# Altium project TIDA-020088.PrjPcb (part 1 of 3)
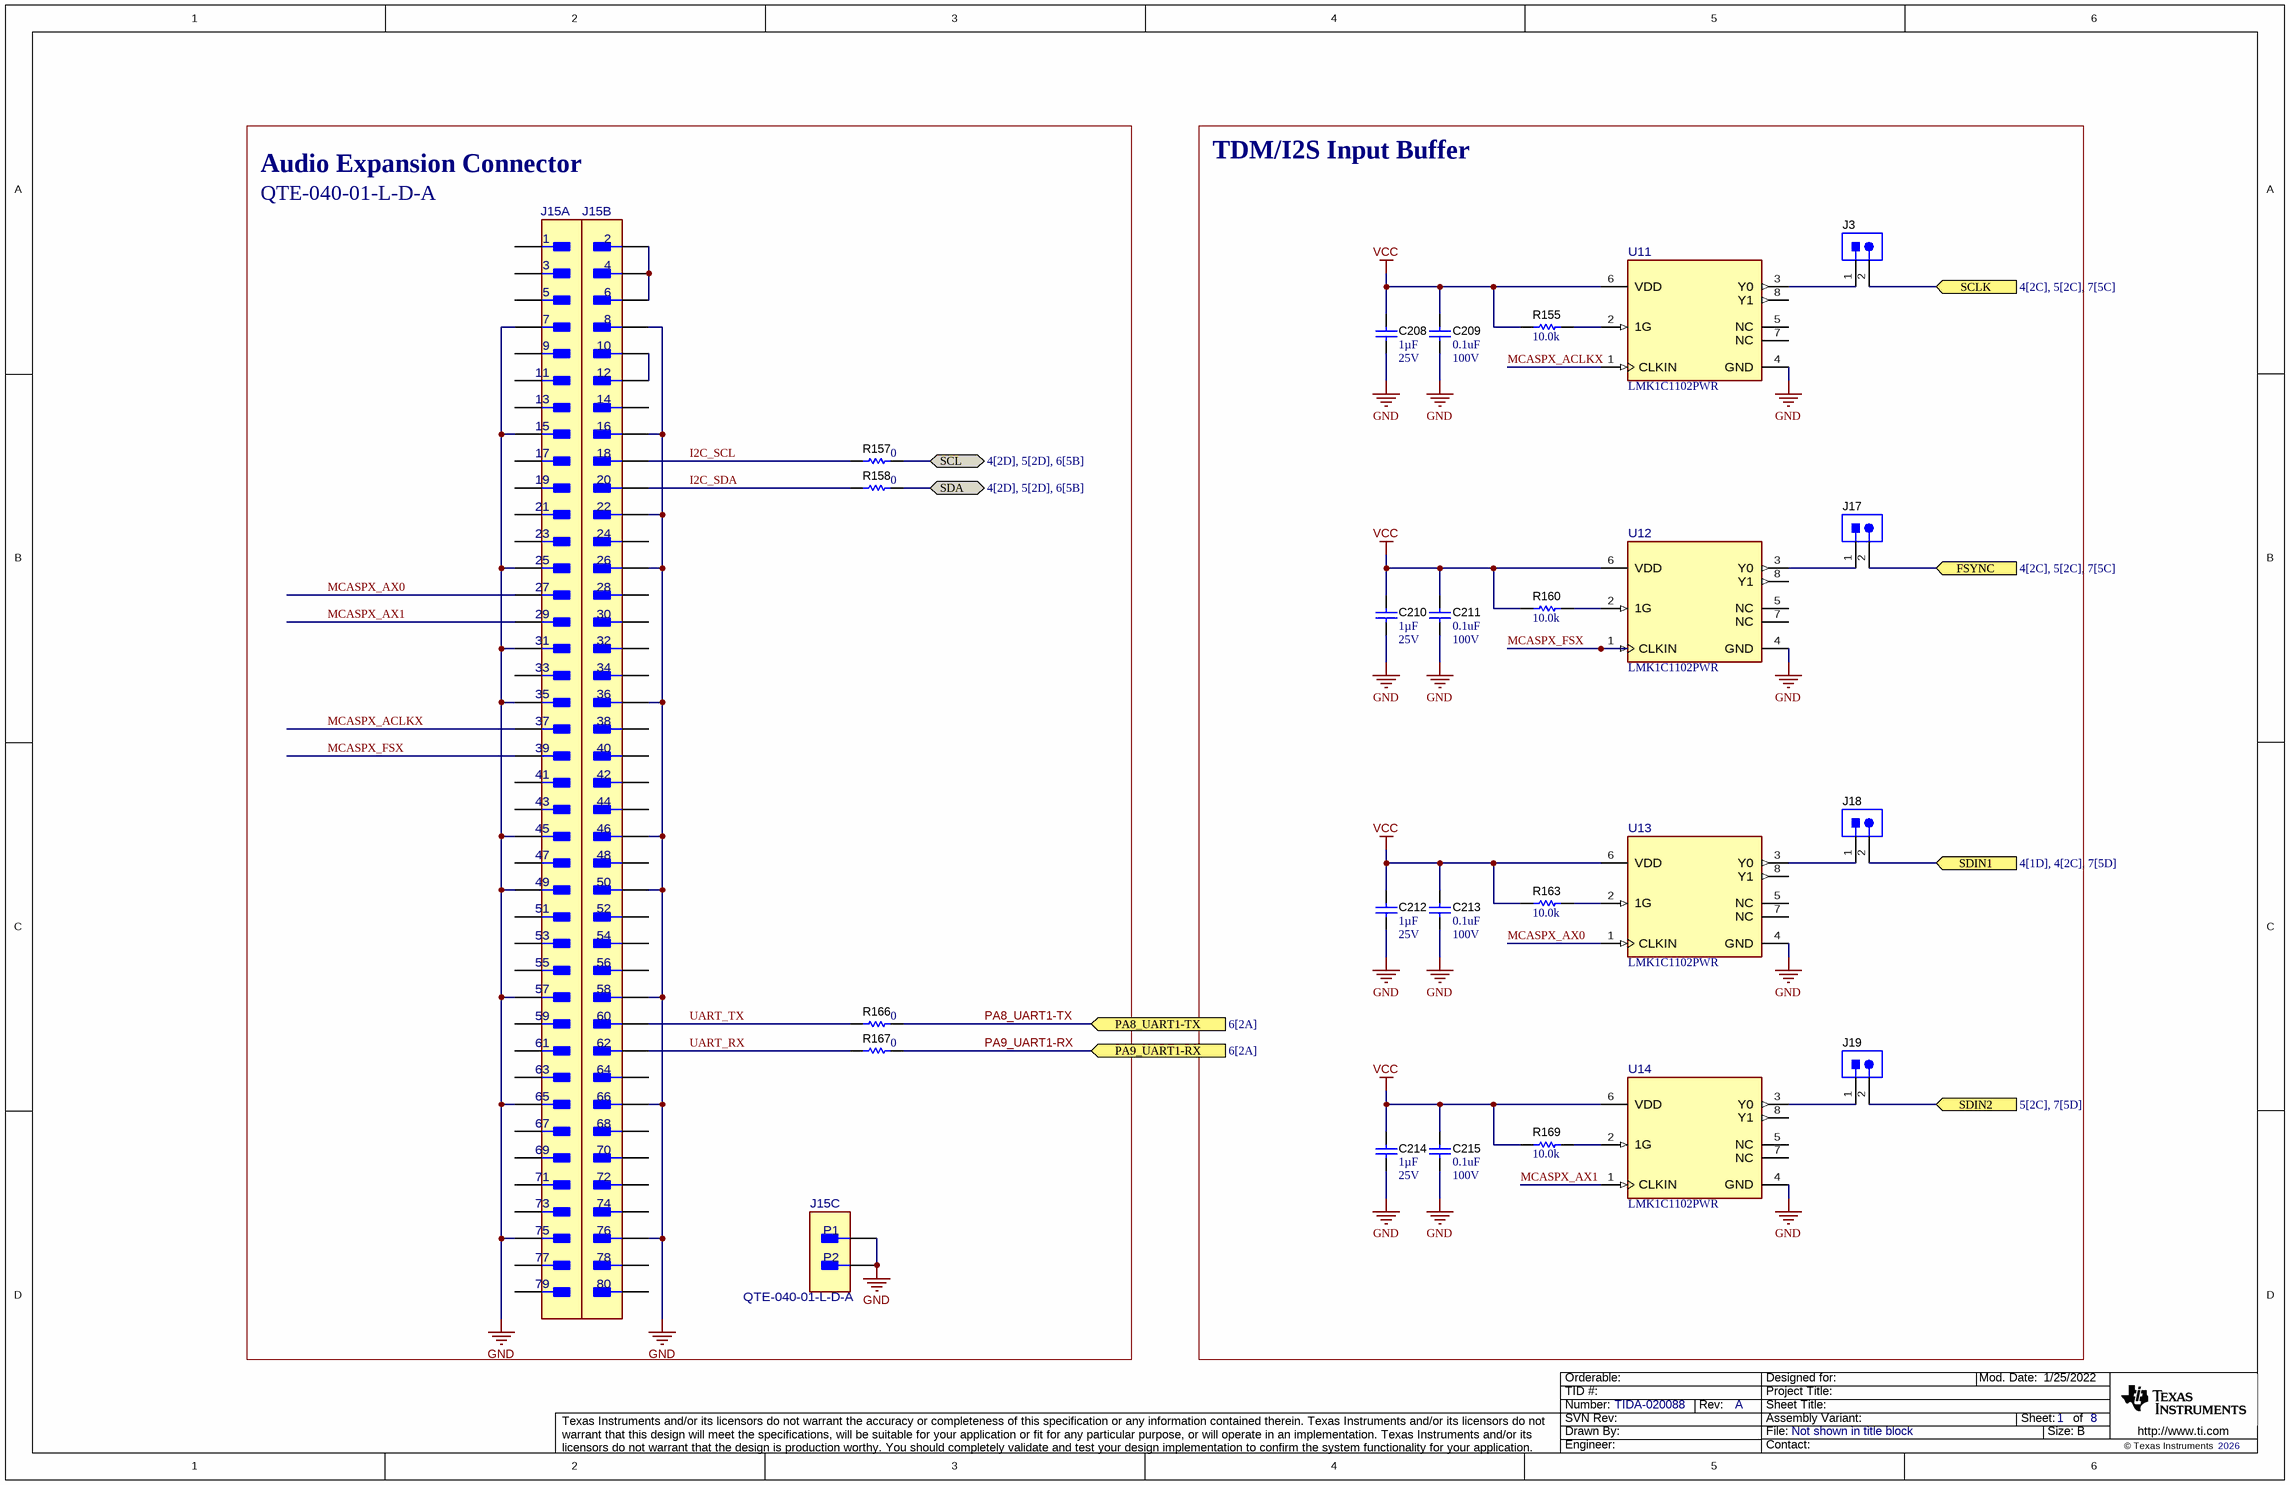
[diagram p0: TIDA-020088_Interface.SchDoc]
SCH_Rev: A; Prj_Number: TIDA-020088; CopyrightYear: 2026
8 sheets, 561 parts. Net scope: flat (ports and power ports of the same name join across sheets).
Board file: TIDA-020088.PCBDOC
Sheets:
  TIDA-020088_Interface.SchDoc
  TIDA-020088_Vbat_Input.SchDoc
  TIDA-020088_LM5125.SchDoc
  TIDA-020088_TAS6684_1.SchDoc
  TIDA-020088_TAS6684_2.SchDoc
  TIDA-020088_MCU-MSPM0G3519SPZR.SchDoc
  TIDA-020088_SPDIF and Interface.SchDoc
  Hardware.SchDoc

## Sheet TIDA-020088_Interface.SchDoc
size 431 x 279 mm; Date: Not shown in title block; ApprovedBy: Not shown in title block; CheckedBy: Not shown in title block; Author: Not shown in title block; CompanyName: Not shown in title block; Engineer: Not shown in title block; Organization: Not shown in title block; Address1: Not shown in title block; Address2: Not shown in title block; Address3: Not shown in title block; Address4: Not shown in title block; DocumentNumber: 2; Revision: Use project parameter SCH_Rev; SheetNumber: 1; SheetTotal: 8; PageSetup: Record=PageOptions¦CenterHorizontal=True¦CenterVertical=True¦PrintScale=1.00¦XCorrection=1.00¦YCorrection=1.00¦PrintKind=0¦BorderSize=5000000¦LeftOffset=0¦BottomOffset=0¦Orientation=2¦PaperLength=1000¦PaperWidth=1000¦Scale=100¦PaperSource=15¦PrintQuality=600¦MediaType=1¦DitherType=10¦PaperKind=Letter¦PrintScaleMode=1

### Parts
C208  Cap_F: 1µF  VDC_V: 25V  [0603]  (hidden comment: GCM188R71E105KA64D)
C209  ValueDisplayed: 0.1uF  VDC_V: 100V  [0603]  (hidden comment: GCJ188R72A104KA01D)
C210  Cap_F: 1µF  VDC_V: 25V  [0603]  (hidden comment: GCM188R71E105KA64D)
C211  ValueDisplayed: 0.1uF  VDC_V: 100V  [0603]  (hidden comment: GCJ188R72A104KA01D)
C212  Cap_F: 1µF  VDC_V: 25V  [0603]  (hidden comment: GCM188R71E105KA64D)
C213  ValueDisplayed: 0.1uF  VDC_V: 100V  [0603]  (hidden comment: GCJ188R72A104KA01D)
C214  Cap_F: 1µF  VDC_V: 25V  [0603]  (hidden comment: GCM188R71E105KA64D)
C215  ValueDisplayed: 0.1uF  VDC_V: 100V  [0603]  (hidden comment: GCJ188R72A104KA01D)
J3  TSW-102-07-G-S  [TSW-102-07-G-S]  (value not drawn)
J15  QTE-040-01-L-D-A  [FP-QTE-040-01-L-D-A_HDR80-MFG]  (parts A,B,C of 3)
J17  TSW-102-07-G-S  [TSW-102-07-G-S]  (value not drawn)
J18  TSW-102-07-G-S  [TSW-102-07-G-S]  (value not drawn)
J19  TSW-102-07-G-S  [TSW-102-07-G-S]  (value not drawn)
R155  ValueDisplayed: 10.0k  [0603]  (hidden comment: CRCW060310K0FKEA)
R157  ValueDisplayed: 0  [0603]  (hidden comment: CRCW06030000Z0EA)
R158  ValueDisplayed: 0  [0603]  (hidden comment: CRCW06030000Z0EA)
R160  ValueDisplayed: 10.0k  [0603]  (hidden comment: CRCW060310K0FKEA)
R163  ValueDisplayed: 10.0k  [0603]  (hidden comment: CRCW060310K0FKEA)
R166  ValueDisplayed: 0  [0603]  (hidden comment: CRCW06030000Z0EA)
R167  ValueDisplayed: 0  [0603]  (hidden comment: CRCW06030000Z0EA)
R169  ValueDisplayed: 10.0k  [0603]  (hidden comment: CRCW060310K0FKEA)
U11  LMK1C1102PWR  [PW0008A-MFG]
U12  LMK1C1102PWR  [PW0008A-MFG]
U13  LMK1C1102PWR  [PW0008A-MFG]
U14  LMK1C1102PWR  [PW0008A-MFG]

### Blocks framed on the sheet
Audio Expansion Connector: J15 R157 R158 R166 R167
TDM/I2S Input Buffer: C208-C215 J3 J17-J19 R155 R160 R163 R169 U11-U14

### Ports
FSYNC (in, see 4[2C], 5[2C], 7[5C]), PA8_UART1-TX (in, see 6[2A]), PA9_UART1-RX (in, see 6[2A]), SCL (bidir, see 4[2D], 5[2D], 6[5B]), SCLK (in, see 4[2C], 5[2C], 7[5C]), SDA (bidir, see 4[2D], 5[2D], 6[5B]), SDIN1 (in, see 4[1D], 4[2C], 7[5D]), SDIN2 (in, see 5[2C], 7[5D])

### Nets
GND: C208.1 C209.1 C210.1 C211.1 C212.1 C213.1 C214.1 C215.1 J15.7 J15.8 J15.15 J15.16 J15.22 J15.25 J15.26 J15.31 J15.35 J15.36 J15.45 J15.46 J15.49 J15.50 J15.57 J15.58 J15.65 J15.66 J15.75 J15.76 J15.P1 J15.P2 U11.4(GND) U12.4(GND) U13.4(GND) U14.4(GND)
VCC: C208.2 C209.2 C210.2 C211.2 C212.2 C213.2 C214.2 C215.2 R155.1 R160.1 R163.1 R169.1 U11.6(VDD) U12.6(VDD) U13.6(VDD) U14.6(VDD)
I2C_SCL: J15.18 R157.1
I2C_SDA: J15.20 R158.1
MCASPX_ACLKX: J15.37 U11.1(CLKIN)
MCASPX_AX0: J15.27 U13.1(CLKIN)
MCASPX_AX1: J15.29 U14.1(CLKIN)
MCASPX_FSX: J15.39 U12.1(CLKIN)
PA8_UART1-TX: R166.2 ; port PA8_UART1-TX
PA9_UART1-RX: R167.2 ; port PA9_UART1-RX
UART_RX: J15.62 R167.1
UART_TX: J15.60 R166.1
NetJ2_2: J3.2 ; port SCLK
NetJ3_1: J3.1 U11.3(Y0)
NetJ4_2: J17.2 ; port FSYNC
NetJ6_2: J18.2 ; port SDIN1
NetJ11_2: R157.2 ; port SCL
NetJ11_3: R158.2 ; port SDA
NetJ15_2: J15.2 J15.4 J15.6
NetJ15_10: J15.10 J15.12
NetJ17_1: J17.1 U12.3(Y0)
NetJ18_1: J18.1 U13.3(Y0)
NetJ19_1: J19.1 U14.3(Y0)
NetJ19_2: J19.2 ; port SDIN2
NetR155_2: R155.2 U11.2(1G)
NetR160_2: R160.2 U12.2(1G)
NetR163_2: R163.2 U13.2(1G)
NetR169_2: R169.2 U14.2(1G)

Not connected (* = marked no-connect by the designer): J15 1 3 5 9 11 13 14 17 19 21 23 24 28 30 32 33 34 38 40 41 42 43 44 47 48 51 52 53 54 55 56 59 61 63 64 67 68 69 70 71 72 73 74 77 78 79 80; U11 5(NC) 7(NC) 8(Y1); U12 5(NC) 7(NC) 8(Y1); U13 5(NC) 7(NC) 8(Y1); U14 5(NC) 7(NC) 8(Y1)

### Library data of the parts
C208 C210 C212 C214 = CMP-0007139-3: CAP, CERM, 1 uF, 25 V, +/- 10%, X7R, AEC-Q200 Grade 1, 0603; Manufacturer: MuRata; TaMin_C: -55°C; Polarized: N; SizeAreaWB_mm2: 4.68; Value1: Unknown; U/M: EA; Value: 1uF; TaMax_C: 125°C; SizeZ_mm: 1; SizeX_mm: 1.6; SizeY_mm: 0.8; SizeArea_mm2: 1.28; AEC Qualified: Y; AEC Category: Q200
C209 C211 C213 C215 = CMP-0064935-4: CAP, CERM, 0.1 uF, 100 V,+/- 10%, X7R, AEC-Q200 Grade 1, 0603; Manufacturer: MuRata; Polarized: N; Value: 0.1uF; U/M: EA; Cap_F: 100nF; Value1: Unknown; TaMin_C: -55°C; TaMax_C: 125°C; SizeAreaWB_mm2: 4.68; SizeZ_mm: 1; SizeX_mm: 1.6; SizeY_mm: 0.8; SizeArea_mm2: 1.28; AEC Qualified: Y; AEC Category: Q200
J3 J17-J19 = CMP-0075405-2: Header, 100mil, 2x1, Gold, TH; Manufacturer: Samtec; Pitch_mm: 2.54; Cert_VDE: N; Gender: Male; Cert_CSA: Y; Voltage_V: 550V; Green_REACh: Passed; Current_A: 6.3A; Green_Lifecycle: Active; Row_Count: 1
J15 = CMP-0091968-1: 80 Position Connector Header, Outer Shroud Contacts Surface Mount Gold; Manufacturer: Samtec; SizeZ_mm: 4.347mm; AEC Qualified: No; Conn Gender: Male; Voltage_V: 225V; Row_Count: 2; ContactFinish: Gold,Nickel; Is Female: yes; Conn Orientation: Vertical; DUT-Pitch_mm: 0.8mm
R155 R160 R163 R169 = CMP-0021998-4: RES, 10.0 k, 1%, 0.1 W, AEC-Q200 Grade 0, 0603; Manufacturer: Vishay-Dale; Power_W: 100mW; TempCo: 100 ppm/C; Value_Code: 10k0; Value: 10.0k; EIA_Code: E96; Res_ohm: 10k; SizeX_mm: 1.6; SizeY_mm: 0.8; SizeZ_mm: 1; Value2: 0.1W; SizeArea_mm2: 1.28; AEC Qualified: Y; VDC_V: 75V; AEC Category: Q200; AEC Grade: 0
R157 R158 R166 R167 = CMP-0025697-4: RES, 0, 5%, 0.1 W, AEC-Q200 Grade 0, 0603; Manufacturer: Vishay-Dale; Power_W: 100mW; TempCo: 200 ppm/C; Value_Code: 0000; Value: 0; SizeX_mm: 1.6; SizeY_mm: 0.8; SizeZ_mm: 1; Value2: 0.1W; SizeArea_mm2: 1.28; AEC Qualified: Y; AEC Category: Q200; EIA_Code: E24; VDC_V: 75V
U11-U14 = CMP-0091149-1: Clock Clock Buffer IC 1:4 250MHz 8-TSSOP (0.173", 4.40mm Width); Manufacturer: Texas Instruments; Standoff Height: 0.05mm; SizeZ_mm: 1.2mm; Propagation Delay: 1.5ns; AEC Qualified: No; Number Of Outputs: 2; Nominal Supply Current: 25-33000uA; TaMin_C: -40°C; Min Supply Voltage: 1.71V; Max Supply Voltage: 3.465V; Number Of Elements: 1; TJmax_C: +150°C; TaMax_C: +125°C

## Sheet TIDA-020088_Vbat_Input.SchDoc
size 431 x 279 mm; Date: Not shown in title block; ApprovedBy: Not shown in title block; CheckedBy: Not shown in title block; Author: Not shown in title block; CompanyName: Not shown in title block; Engineer: Not shown in title block; Organization: Not shown in title block; Address1: Not shown in title block; Address2: Not shown in title block; Address3: Not shown in title block; Address4: Not shown in title block; DocumentNumber: 2; Revision: Use project parameter SCH_Rev; SheetNumber: 2; SheetTotal: 8; PageSetup: Record=PageOptions¦CenterHorizontal=True¦CenterVertical=True¦PrintScale=1.00¦XCorrection=1.00¦YCorrection=1.00¦PrintKind=0¦BorderSize=5000000¦LeftOffset=0¦BottomOffset=0¦Orientation=2¦PaperLength=1000¦PaperWidth=1000¦Scale=100¦PaperSource=15¦PrintQuality=600¦MediaType=1¦DitherType=10¦PaperKind=Letter¦PrintScaleMode=1
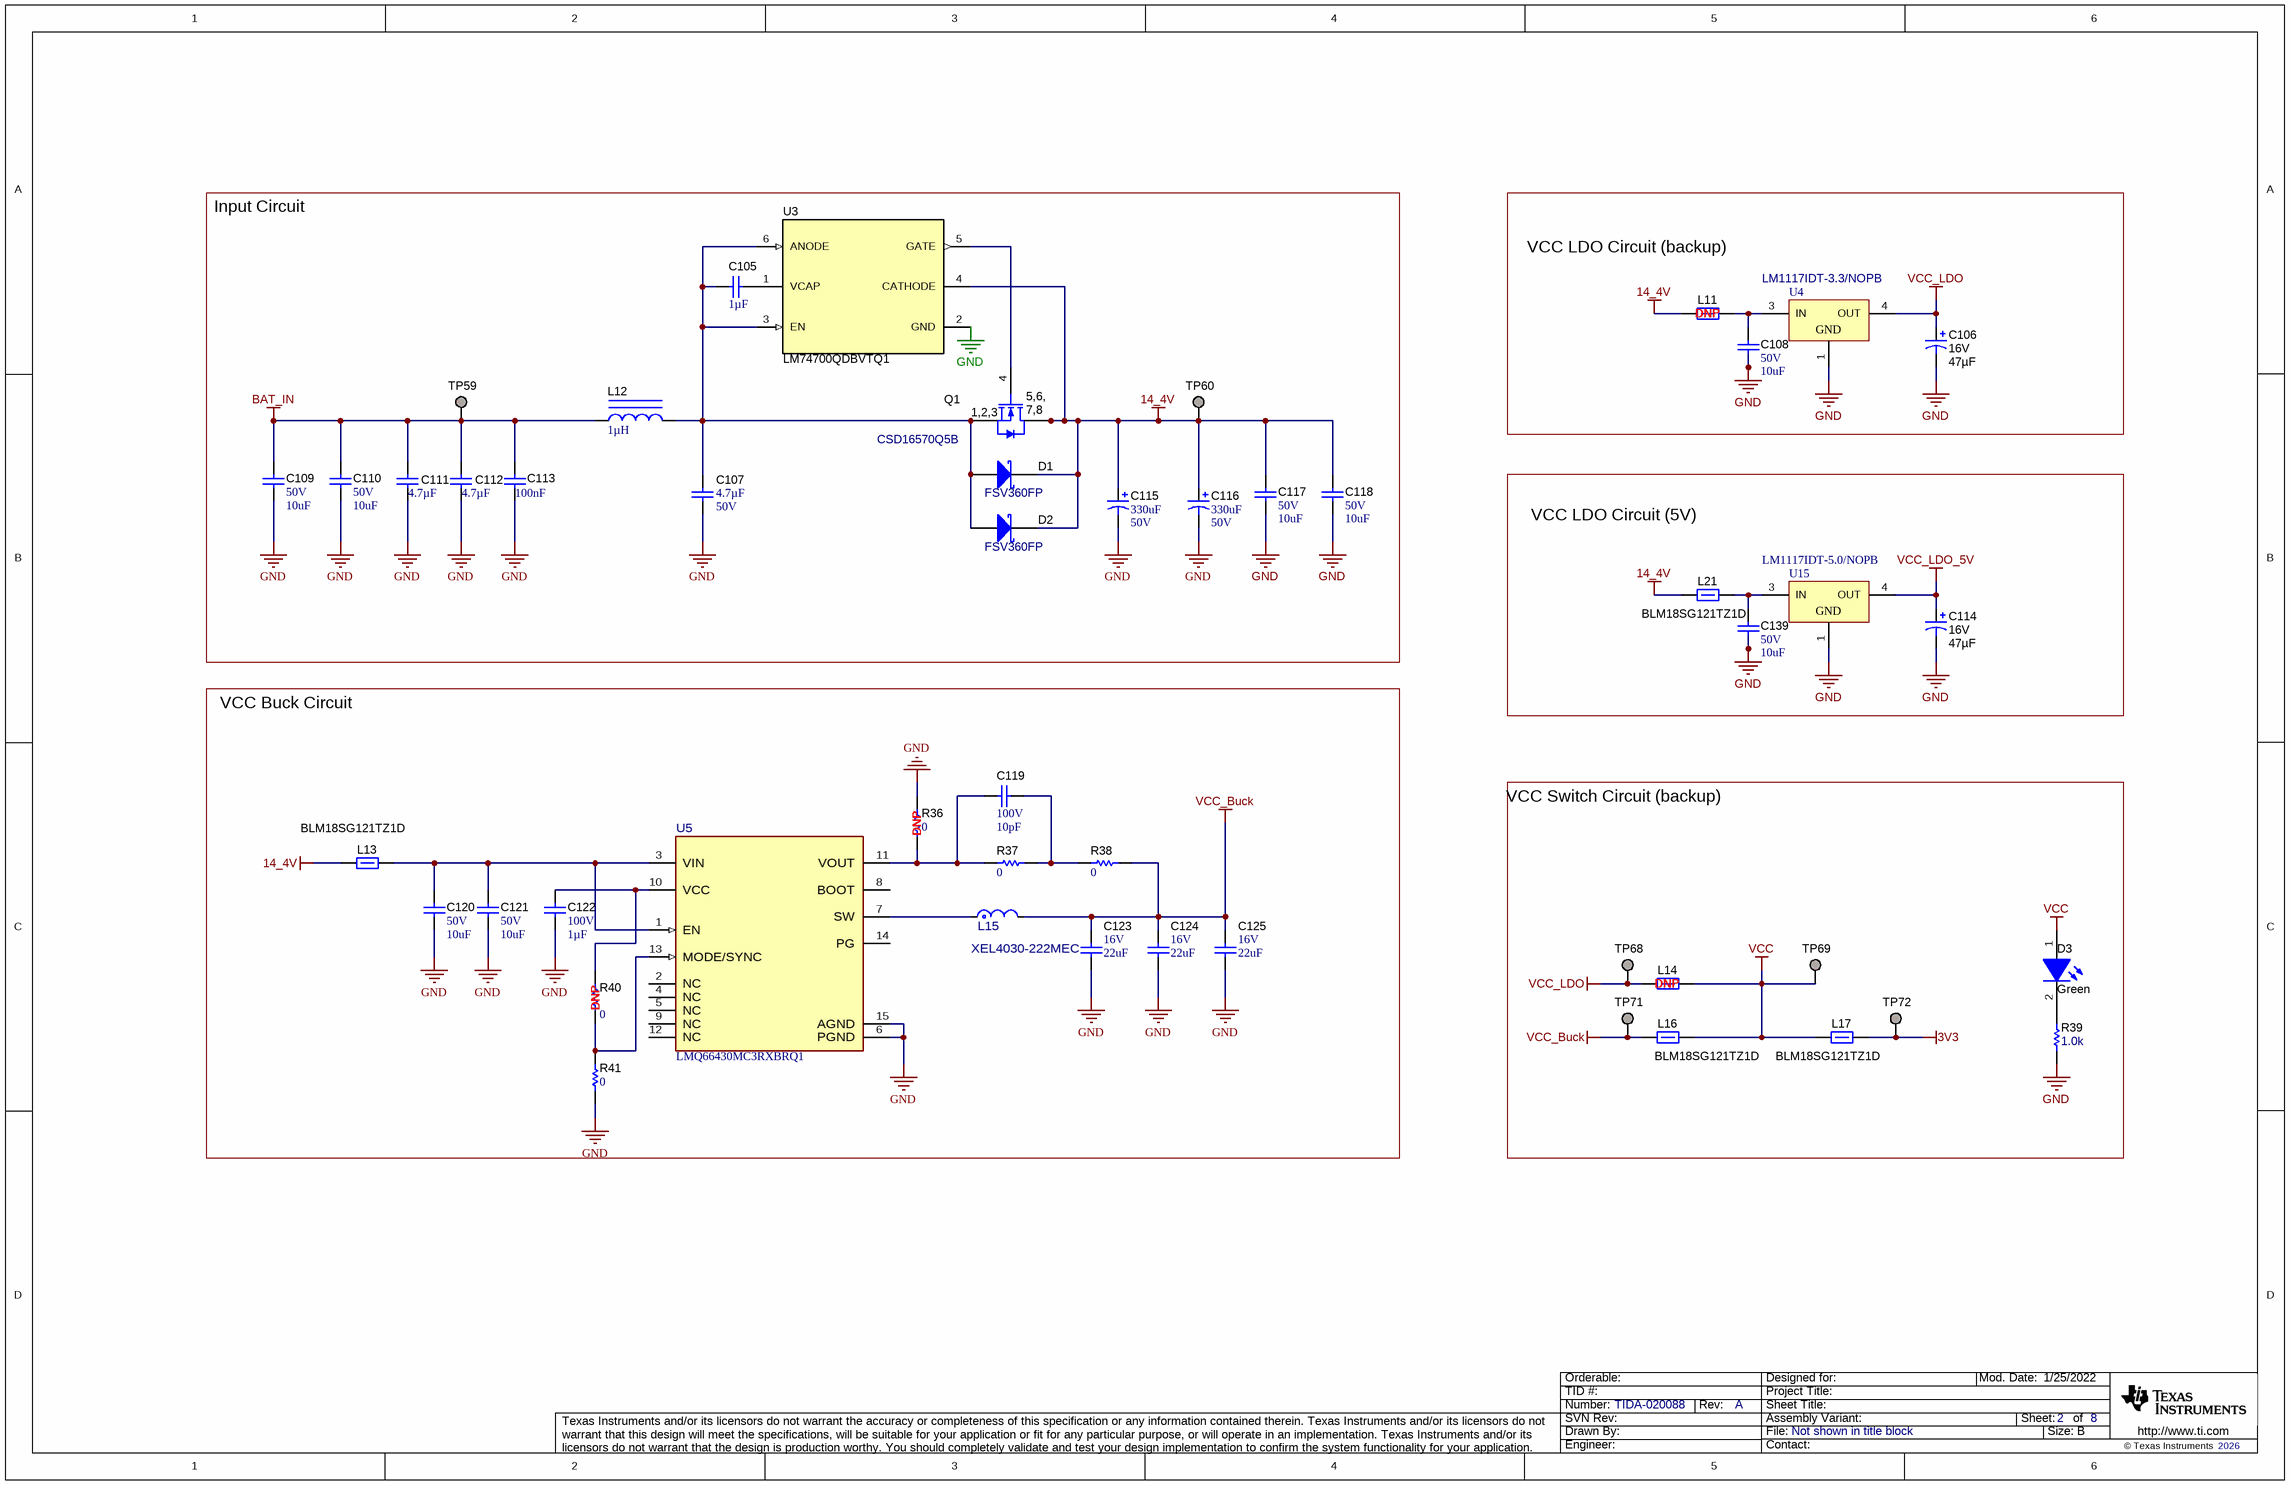
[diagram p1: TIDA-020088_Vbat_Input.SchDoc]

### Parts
C105  Cap_F: 1µF  [0603]  (hidden comment: GCM188R71E105KA64D)
C106  VDC_V: 16V  ValueDisplayed: 47µF  [Panasonic_B]  (hidden comment: EEE-FT1C470AR)
C107  VDC_V: 50V  ValueDisplayed: 4.7µF  [1210_270]  (hidden comment: GCM32ER71H475KA55L)
C108  VDC_V: 50V  ValueDisplayed: 10uF  [1210_280]  (hidden comment: UMK325AB7106KMHT)
C109  VDC_V: 50V  ValueDisplayed: 10uF  [1210_280]  (hidden comment: UMK325AB7106KMHT)
C110  VDC_V: 50V  ValueDisplayed: 10uF  [1210_280]  (hidden comment: UMK325AB7106KMHT)
C111  ValueDisplayed: 4.7µF  [1210_270]  (hidden comment: GCM32ER71H475KA55L)
C112  ValueDisplayed: 4.7µF  [1210_270]  (hidden comment: GCM32ER71H475KA55L)
C113  Cap_F: 100nF  [0603]  (hidden comment: GCJ188R72A104KA01D)
C114  VDC_V: 16V  ValueDisplayed: 47µF  [Panasonic_B]  (hidden comment: EEE-FT1C470AR)
C115  ValueDisplayed: 330uF  VDC_V: 50V  [Nichicon_1000x1000]  (hidden comment: UCM1H331MNL1GS)
C116  ValueDisplayed: 330uF  VDC_V: 50V  [Nichicon_1000x1000]  (hidden comment: UCM1H331MNL1GS)
C117  VDC_V: 50V  ValueDisplayed: 10uF  [1210_280]  (hidden comment: UMK325AB7106KMHT)
C118  VDC_V: 50V  ValueDisplayed: 10uF  [1210_280]  (hidden comment: UMK325AB7106KMHT)
C119  VDC_V: 100V  ValueDisplayed: 10pF  [0603]  (hidden comment: GCM1885C2A100JA16D)
C120  VDC_V: 50V  ValueDisplayed: 10uF  [1210_280]  (hidden comment: UMK325AB7106KMHT)
C121  VDC_V: 50V  ValueDisplayed: 10uF  [1210_280]  (hidden comment: UMK325AB7106KMHT)
C122  VDC_V: 100V  ValueDisplayed: 1µF  [1206]  (hidden comment: GCJ31CR72A105KA01K)
C123  VDC_V: 16V  ValueDisplayed: 22uF  [1210_280]  (hidden comment: CGA6P1X7R1C226M250AC)
C124  VDC_V: 16V  ValueDisplayed: 22uF  [1210_280]  (hidden comment: CGA6P1X7R1C226M250AC)
C125  VDC_V: 16V  ValueDisplayed: 22uF  [1210_280]  (hidden comment: CGA6P1X7R1C226M250AC)
C139  VDC_V: 50V  ValueDisplayed: 10uF  [1210_280]  (hidden comment: UMK325AB7106KMHT)
D1  FSV360FP  [SOD-123HE]
D2  FSV360FP  [SOD-123HE]
D3  value Green  [LTST-C170KGKT_Green]  (hidden comment: CMP-0002888-1)
L11  DNP  [0603]  (no BOM)
L12  ValueDisplayed: 1µH  [SRP2313AA]  (hidden comment: SRP2313AA-1R0M)
L13  BLM18SG121TZ1D  [0603]
L14  DNP  [0603]  (no BOM)
L15  XEL4030-222MEC  [FP-XEL4030-222MEC_SMT2_4MM0_4MM0-MFG]
L16  BLM18SG121TZ1D  [0603]
L17  BLM18SG121TZ1D  [0603]
L21  BLM18SG121TZ1D  [0603]
Q1  CSD16570Q5B  [DNK0008A]
R36  DNP  ValueDisplayed: 0  [0603]  (no BOM)
R37  ValueDisplayed: 0  [0603]  (hidden comment: CRCW06030000Z0EA)
R38  ValueDisplayed: 0  [0603]  (hidden comment: CRCW06030000Z0EA)
R39  ValueDisplayed: 1.0k  [0402L]  (hidden comment: CRCW04021K00JNED)
R40  DNP  ValueDisplayed: 0  [0603]  (no BOM)
R41  ValueDisplayed: 0  [0603]  (hidden comment: CRCW06030000Z0EA)
TP59  TP_SM_1MM  [TP_SM_1MM]  (value not drawn)  (no BOM)
TP60  TP_SM_1MM  [TP_SM_1MM]  (value not drawn)  (no BOM)
TP68  TP_SM_1MM  [TP_SM_1MM]  (value not drawn)  (no BOM)
TP69  TP_SM_1MM  [TP_SM_1MM]  (value not drawn)  (no BOM)
TP71  TP_SM_1MM  [TP_SM_1MM]  (value not drawn)  (no BOM)
TP72  TP_SM_1MM  [TP_SM_1MM]  (value not drawn)  (no BOM)
U3  LM74700QDBVTQ1  [DBV0006A_N]
U4  LM1117IDT-3.3/NOPB  [NDP0003B_N]
U5  LMQ66430MC3RXBRQ1  [RXB0014A-MFG]
U15  LM1117IDT-5.0/NOPB  [NDP0003B]

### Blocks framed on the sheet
Input Circuit: C105 C107 C109-C113 C115-C118 D1 D2 L12 Q1 TP59 TP60 U3
VCC LDO Circuit (backup): C106 C108 L11 U4
VCC LDO Circuit (5V): C114 C139 L21 U15
VCC Buck Circuit: C119-C125 L13 L15 R36-R38 R40 R41 U5
VCC Switch Circuit (backup): D3 L14 L16 L17 R39 TP68 TP69 TP71 TP72

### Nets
3V3: L17.2 TP72.1
14_4V: C115.1(+) C116.1(+) C117.1 C118.1 D1.1(K) D2.1(K) L11.1 L13.1 L21.1 Q1.5(D) Q1.6(D) Q1.7(D) Q1.8(D) Q1.9(D) TP60.1 U3.4(CATHODE)  [project net BIAS]
BAT_IN: C109.1 C110.1 C111.1 C112.1 C113.1 L12.1 TP59.1
GND: C106.2(-) C107.2 C108.2 C109.2 C110.2 C111.2 C112.2 C113.2 C114.2(-) C115.2(-) C116.2(-) C117.2 C118.2 C120.2 C121.2 C122.2 C123.2 C124.2 C125.2 C139.2 R36.2 R39.1 R41.1 U3.2(GND) U4.1(GND) U5.6(PGND) U5.15(AGND) U15.1(GND)
VCC: D3.1(A) L14.2 L16.2 L17.1 TP69.1
VCC_Buck: C123.1 C124.1 C125.1 L15.2 L16.1 R38.2 TP71.1
VCC_LDO: C106.1(+) L14.1 TP68.1 U4.4(OUT)
VCC_LDO_5V: C114.1(+) U15.4(OUT)
NetC105_1: C105.1 C107.1 D1.2(A) D2.2(A) L12.2 Q1.1(S) Q1.2(S) Q1.3(S) U3.3(EN) U3.6(ANODE)
NetC105_2: C105.2 U3.1(VCAP)
NetC108_1: C108.1 L11.2 U4.3(IN)
NetC119_1: C119.1 R36.1 R37.1 U5.11(VOUT)
NetC119_2: C119.2 R37.2 R38.1
NetC120_1: C120.1 C121.1 L13.2 U5.1(EN) U5.3(VIN)
NetC122_1: C122.1 R40.1 U5.10(VCC)
NetC139_1: C139.1 L21.2 U15.3(IN)
NetD3_2: D3.2(K) R39.2
NetL15_1: L15.1 U5.7(SW)
NetQ1_4: Q1.4(G) U3.5(GATE)
NetR40_2: R40.2 R41.2 U5.13(MODE/SYNC)

Not connected (* = marked no-connect by the designer): U5 2(NC) 4(NC) 5(NC) 8(BOOT) 9(NC) 12(NC) 14(PG)

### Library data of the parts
C105 = CMP-0007139-4: CAP, CERM, 1 uF, 25 V, +/- 10%, X7R, AEC-Q200 Grade 1, 0603; Manufacturer: MuRata; Value: 1uF; SizeZ_mm: 1; AEC Qualified: Y; VDC_V: 25V; TaMin_C: -55°C; Polarized: N; SizeAreaWB_mm2: 4.68; Value1: Unknown; U/M: EA; TaMax_C: 125°C; SizeX_mm: 1.6; SizeY_mm: 0.8; SizeArea_mm2: 1.28; AEC Category: Q200
C106 C114 = CMP-0860542-1: CAP, AL, 47 µF, 16 V, +/- 20%, 0.85 ohm, AEC-Q200 Grade 2, SMD; Manufacturer: Panasonic; AEC Qualified: Y; AEC Grade: 2; U/M: EA; SizeZ_mm: 6.1; ESR_ohm: 0.85; SizeY_mm: 4.3; CompType: Capacitor; TaMax_C: 105°C; TaMin_C: -55°C; IRMS_A: 160mA; SizeArea_mm2: 18.49; Value: 47uF; SizeAreaWB_mm2: 28.09; AEC Category: Q200; Cap_Case: B
C107 = CMP-0750153-1: CAP, CERM, 4.7 µF, 50 V,+/- 10%, X7R, AEC-Q200 Grade 1, 1210; Manufacturer: MuRata; TaMin_C: -55°C; Polarized: N; SizeAreaWB_mm2: 14.7; U/M: EA; Value: 4.7uF; TaMax_C: 125°C; SizeZ_mm: 2.7; SizeX_mm: 3.2; SizeY_mm: 2.5; Cap_Case: 1210; SizeArea_mm2: 8; AEC Qualified: Y; AEC Category: Q200; AEC Grade: 1
C108-C110 C117 C118 C120 C121 C139 = CMP-0009258-2: CAP, CERM, 10 uF, 50 V, +/- 10%, X7R, AEC-Q200 Grade 1, 1210; Manufacturer: Taiyo Yuden; Value: 10uF; SizeZ_mm: 2.8; AEC Qualified: Y; Cap_F: 10µF; AEC Grade: 1; TaMin_C: -55°C; Polarized: N; SizeAreaWB_mm2: 14.7; Value1: Unknown; U/M: EA; TaMax_C: 125°C; SizeX_mm: 3.2; SizeY_mm: 2.5; Cap_Case: 1210; SizeArea_mm2: 8; AEC Category: Q200
C111 C112 = CMP-0750153-1: CAP, CERM, 4.7 µF, 50 V,+/- 10%, X7R, AEC-Q200 Grade 1, 1210; Manufacturer: MuRata; TaMin_C: -55°C; Polarized: N; SizeAreaWB_mm2: 14.7; U/M: EA; Value: 4.7uF; TaMax_C: 125°C; SizeZ_mm: 2.7; SizeX_mm: 3.2; SizeY_mm: 2.5; Cap_Case: 1210; Value2: 50V; SizeArea_mm2: 8; AEC Qualified: Y; AEC Category: Q200; AEC Grade: 1
C113 = CMP-0064935-4: CAP, CERM, 0.1 uF, 100 V,+/- 10%, X7R, AEC-Q200 Grade 1, 0603; Manufacturer: MuRata; TaMin_C: -55°C; Polarized: N; SizeAreaWB_mm2: 4.68; Value1: Unknown; U/M: EA; Value: 0.1uF; TaMax_C: 125°C; SizeZ_mm: 1; SizeX_mm: 1.6; SizeY_mm: 0.8; Value2: 100V; SizeArea_mm2: 1.28; AEC Qualified: Y; AEC Category: Q200
C115 C116 = CMP-0064900-1: CAP, AL, 330 uF, 50 V, +/- 20%, SMD; Manufacturer: Nichicon; AEC Qualified: N; Cap_F: 330µF; IRMS_A: 900mA; SizeZ_mm: 10.8; Value: 330uF; TaMin_C: -55°C; Polarized: Y; SizeAreaWB_mm2: 151.29; Value1: Unknown; U/M: EA; TaMax_C: 105°C; SizeX_mm: 10.3; Cap_Case: 10x10mm; SizeArea_mm2: 106.09; CompType: Capacitor; AEC Category: Q200
C119 = CMP-0084283-1: CAP, CERM, 10 pF, 100 V,+/- 5%, C0G/NP0, AEC-Q200 Grade 1, 0603; Manufacturer: MuRata; TaMin_C: -55°C; Polarized: N; SizeAreaWB_mm2: 4.68; U/M: EA; Value: 10pF; TaMax_C: 125°C; SizeZ_mm: 1; SizeX_mm: 1.6; SizeY_mm: 0.8; SizeArea_mm2: 1.28; AEC Qualified: Y; AEC Category: Q200
C122 = CMP-0750040-1: CAP, CERM, 1 µF, 100 V,+/- 10%, X7R, AEC-Q200 Grade 1, 1206; Manufacturer: MuRata; Value: 1uF; U/M: EA; SizeX_mm: 3.2; Polarized: N; TaMin_C: -55°C; SizeZ_mm: 1.35; SizeY_mm: 1.6; AEC Category: Q200; SizeArea_mm2: 5.12; TaMax_C: 125°C; AEC Grade: 1; AEC Qualified: Y; SizeAreaWB_mm2: 10.92
C123-C125 = CMP-0009154-2: CAP, CERM, 22 uF, 16 V, +/- 20%, X7R, AEC-Q200 Grade 1, 1210; Manufacturer: TDK; Cap_F: 22µF; AEC Qualified: Y; AEC Grade: 1; Value: 22uF; SizeZ_mm: 2.8; TaMin_C: -55°C; ESR_ohm: 2.582m; Polarized: N; SizeAreaWB_mm2: 14.7; Value1: 0.002582 ohm; U/M: EA; TaMax_C: 125°C; SizeX_mm: 3.2; SizeY_mm: 2.5; SizeArea_mm2: 8; IRMS_A: 4.5756A; AEC Category: Q200
D1 D2 = CMP-0028825-2: Diode, Schottky, 60 V, 3 A, AEC-Q101, SOD-123HE; Manufacturer: Fairchild Semiconductor; Vf_V: 650mV; SizeArea_mm2: 6.66; Vr_V: 60V; Green_Lifecycle: Not Set; Value: 60V; Value1: 3A; Green_REACh: Incomplete; SizeY_mm: 1.8; Value2: 0.65V; TJmax_C: 150°C; AEC Category: Q101; SizeAreaWB_mm2: 13.16; SizeZ_mm: 1; AEC Qualified: Y; SizeX_mm: 3.7
D3 = CMP-0002888-1: LED, Green, SMD; Manufacturer: Lite-On; PartNumber: LTST-C170KGKT; Type: AlInGaP; Vf_V: 2V; Io_A: 20mA; Value1: W; U/M: EA
L11 L14 = CMP-0084877-1: Inductor, Ferrite Bead, Ferrite, 3 A, 120 ohm, AEC-Q200 Grade 1, SMD; Manufacturer: MuRata; PartNumber: BLM18SG121TZ1D; SizeAreaWB_mm2: 4.68; DCR_ohm: 120; Value1: 120 ohm; Imax_A: 3A; SizeZ_mm: 1; SizeX_mm: 1.6; SizeY_mm: 0.8; SizeArea_mm2: 1.28; AEC Qualified: Y; AEC Category: Q200
L12 = CMP-0081035-1: Inductor, Shielded, Metal Composite, 1 µH, 60 A, 0.00095 ohm, AEC-Q200 Grade 0, SMD; Manufacturer: Bourns; Isat: 60A @ 30% inductance drop; Irms: 70A @ 40C rise; SizeAreaWB_mm2: 612; DCR_ohm: 950µ; Value: 1uH; Imax_A: 60A; SizeZ_mm: 13; SizeX_mm: 23.5; SizeY_mm: 22; SizeArea_mm2: 517; AEC Qualified: Y; AEC Grade: 0; AEC Category: Q200
L13 L16 L17 L21 = CMP-0084877-1: Inductor, Ferrite Bead, Ferrite, 3 A, 120 ohm, AEC-Q200 Grade 1, SMD; Manufacturer: MuRata; SizeAreaWB_mm2: 4.68; DCR_ohm: 120; Value1: 120 ohm; Imax_A: 3A; SizeZ_mm: 1; SizeX_mm: 1.6; SizeY_mm: 0.8; SizeArea_mm2: 1.28; AEC Qualified: Y; AEC Category: Q200
L15 = CMP-0120010-1: Ultra-Low Loss Shielded Power Inductors 2.2µH ±20% 7.8A 22.1mOhms; Manufacturer: Coilcraft; AEC Grade: Grade 1; AEC Qualified: Yes; DCR_ohm: 22.1m; Isat: 6.1A; Material: Composite; SizeZ_mm: 3.1mm; Value: 2.2uH; Self Resonant Frequency: 40MHz; Shrouded: true; TaMax_C: +125°C; TaMin_C: -40°C; Test Frequency: 1MHz
Q1 = CMP-0000274-1: MOSFET, N-CH, 25 V, 100 A, DNK0008A (VSON-CLIP-8); Alternate Manufacturer: None; Manufacturer: Texas Instruments; SizeZ_mm: 1; ChType: N; Value2: 192 nC; Value1: 0; VdsMax_V: 25V; SizeX_mm: 6; SizeY_mm: 5; Vgs_V: 20V; Value: 25V; Rdson45_ohm: 800µ; SizeArea_mm2: 30; AEC Category: Q101; IdsMax_A: 100A; SizeAreaWB_mm2: 56; U/M: EA; QgTyp_nC: 192
R36 R40 = CMP-0025697-4: RES, 0, 5%, 0.1 W, AEC-Q200 Grade 0, 0603; Manufacturer: Vishay-Dale; PartNumber: CRCW06030000Z0EA; Power_W: 100mW; TempCo: 200 ppm/C; Value_Code: 0000; Value: 0; EIA_Code: E24; SizeX_mm: 1.6; SizeY_mm: 0.8; SizeZ_mm: 1; Value2: 0.1W; SizeArea_mm2: 1.28; AEC Qualified: Y; AEC Category: Q200; VDC_V: 75V
R37 R38 R41 = CMP-0025697-4: RES, 0, 5%, 0.1 W, AEC-Q200 Grade 0, 0603; Manufacturer: Vishay-Dale; Power_W: 100mW; TempCo: 200 ppm/C; Value_Code: 0000; Value: 0; EIA_Code: E24; SizeX_mm: 1.6; SizeY_mm: 0.8; SizeZ_mm: 1; Value2: 0.1W; SizeArea_mm2: 1.28; AEC Qualified: Y; AEC Category: Q200; VDC_V: 75V
R39 = CMP-0026852-3: RES, 1.0 k, 5%, 0.063 W, AEC-Q200 Grade 0, 0402; Manufacturer: Vishay-Dale; Power_W: 63mW; TempCo: 200 ppm/C; Value_Code: 1k00; Value: 1.0k; EIA_Code: E24; Res_ohm: 1k; SizeX_mm: 1; SizeY_mm: 0.5; SizeZ_mm: 0.6; Value2: 0.063W; CompType: Resistor; AEC Qualified: Y; VDC_V: 50V; AEC Category: Q200; AEC Grade: 0
TP59 TP60 TP68 TP69 TP71 TP72 = CMP-0003825-1: 1mm Test Point, SMT; Manufacturer: Any
U3 = CMP-0079180-1: Low Iq Always ON Smart Diode Controller, DBV0006A (SOT-23-6); Alternate PartNumber: LM74700QDBVRQ1; Alternate Manufacturer: Texas Instruments; SizeAreaWB_mm2: 14.82; SizeZ_mm: 1.45; SizeX_mm: 2.8; SizeY_mm: 2.9; SizeArea_mm2: 8.12; CompType: IC; AEC Qualified: Y; AEC Category: Q200
U4 = CMP-0070332-1: 800mA Low-Dropout Linear Regulator, 3-pin TO-252, Pb-Free; Manufacturer: Texas Instruments; CompType: LDO IC; PackageTopMarking: NSUZXYTT*LM1117*IDT-3.3; PowerWise: N
U5 = CMP-0093580-1: 3 V-36 V, 3-A Synchronous Buck Converter Optimized for Ultra Low EMI and Light Load Efficiency; Manufacturer: Texas Instruments; SizeZ_mm: 0.7mm; Min Supply Voltage: 3.6V; Number Of Outputs: 1; TaMin_C: -40°C; AEC Qualified: Yes; Output Voltage: 1-34.2V; Max Duty Cycle: 98%; Output Type: AdjustableProgrammable; Switching Frequency: 0.25-2.2MHz; Nominal Supply Current: 0.2-3uA; Max Supply Voltage: 36V; AEC Grade: Grade 1; Standoff Height: 0mm; TJmax_C: +150°C; TaMax_C: +125°C
U15 = CMP-0070337-2: Space Saving 800mA Low-Dropout Linear Regulator with Internal Current Limit, NDP0003B (TO-252-3); Manufacturer: Texas Instruments; CompType: IC; AEC Category: Q200; AEC Qualified: N; SizeAreaWB_mm2: 102.2; SizeArea_mm2: 65.2; SizeX_mm: 9.91; SizeY_mm: 6.58; SizeZ_mm: 2.55

## Sheet TIDA-020088_LM5125.SchDoc: Schematc
size 558 x 431 mm; Date: Not shown in title block; ApprovedBy: Not shown in title block; CheckedBy: Not shown in title block; Author: Not shown in title block; CompanyName: Not shown in title block; DrawnBy: Harry Hofner; Engineer: Not shown in title block; Organization: Not shown in title block; Address1: Not shown in title block; Address2: Not shown in title block; Address3: Not shown in title block; Address4: Not shown in title block; DocumentNumber: 1; Revision: Use project parameter SCH_Rev; SheetNumber: 4; SheetTotal: 8; PageSetup: Record=PageOptions¦CenterHorizontal=True¦CenterVertical=True¦PrintScale=1.00¦XCorrection=1.00¦YCorrection=1.00¦PrintKind=0¦BorderSize=5000000¦LeftOffset=0¦BottomOffset=0¦Orientation=2¦PaperLength=1000¦PaperWidth=1000¦Scale=100¦PaperSource=15¦PrintQuality=600¦MediaType=1¦DitherType=10¦PaperKind=Letter¦PrintScaleMode=1
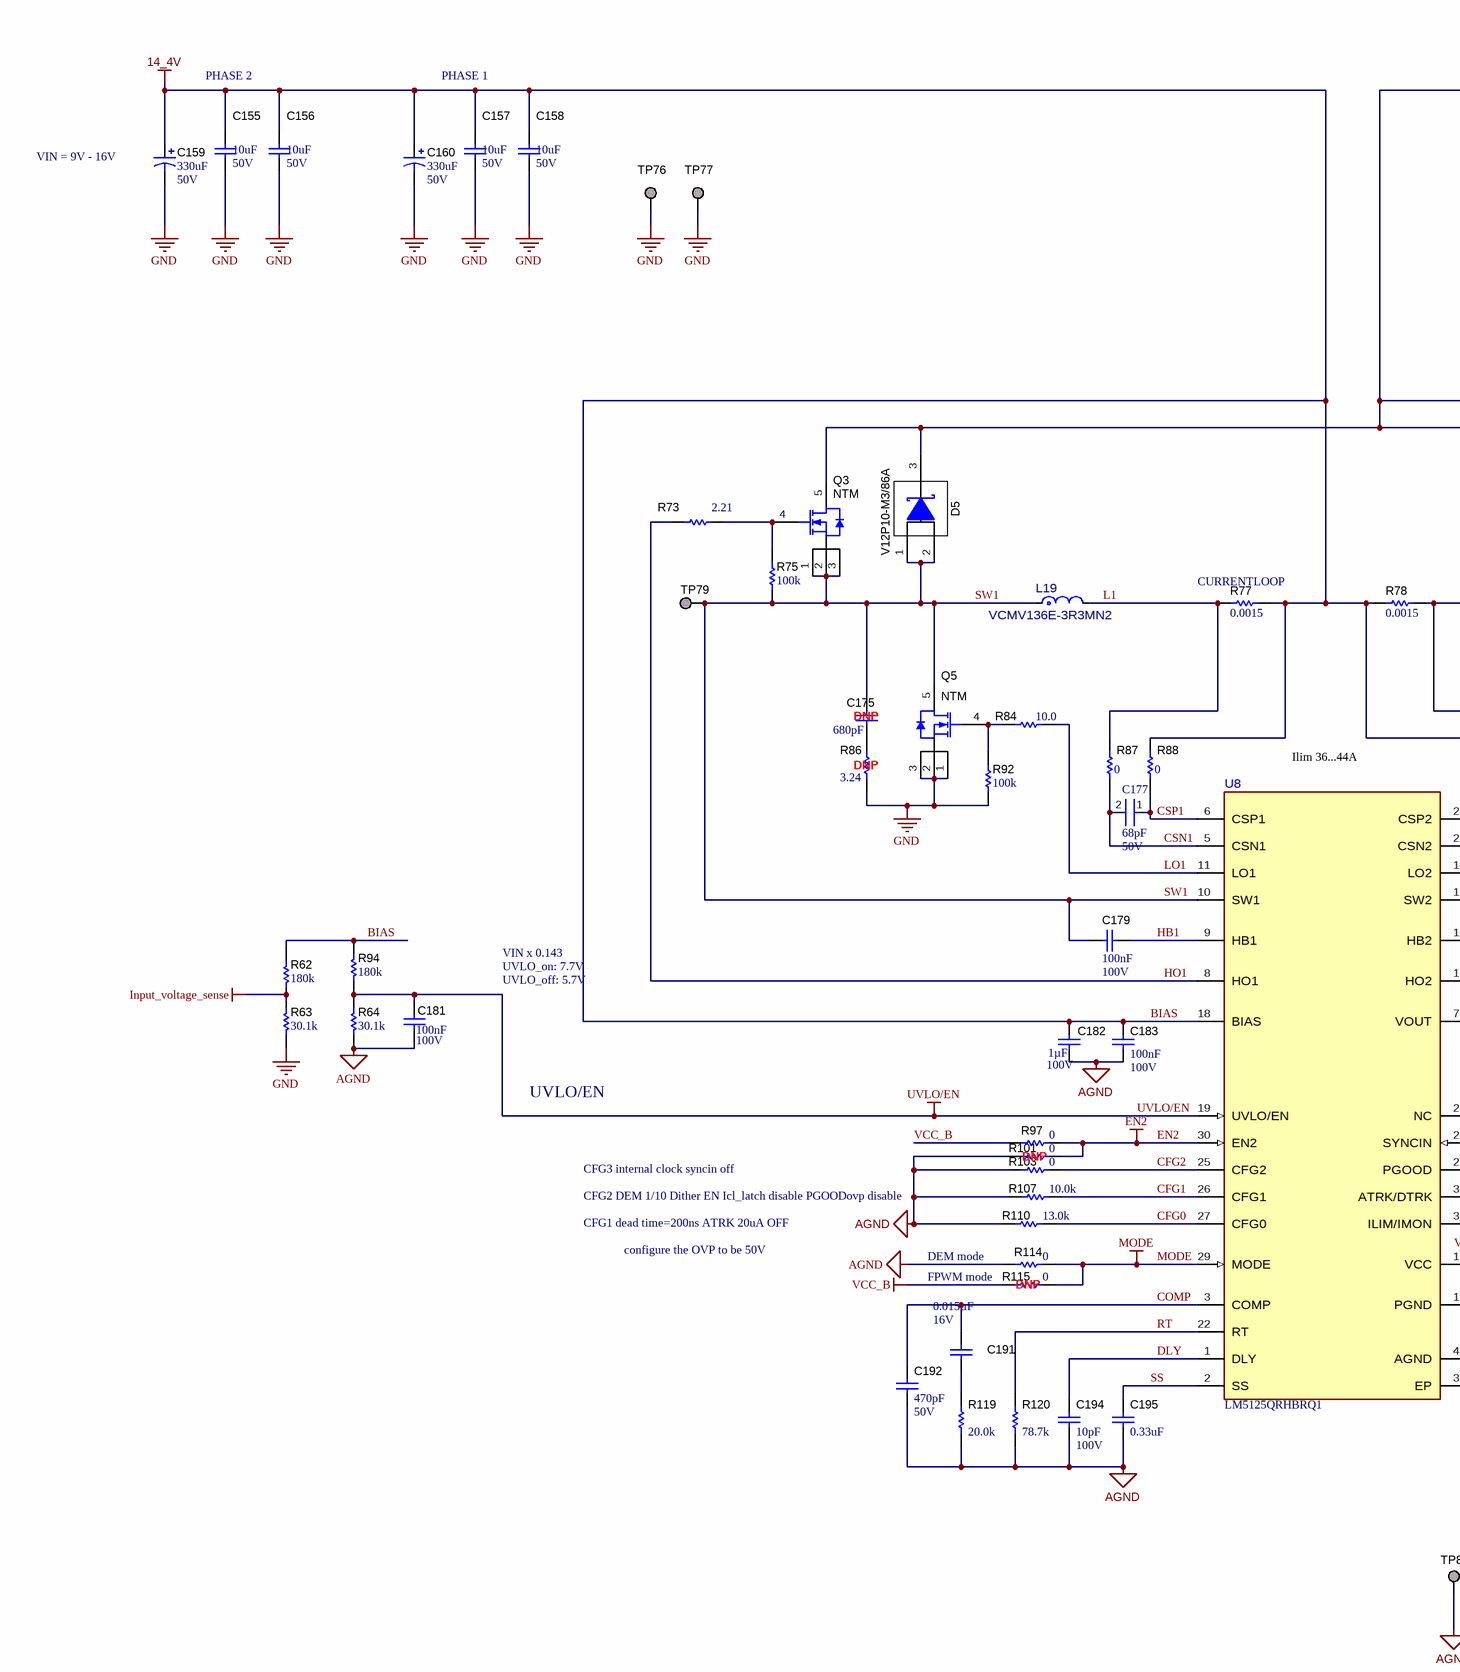
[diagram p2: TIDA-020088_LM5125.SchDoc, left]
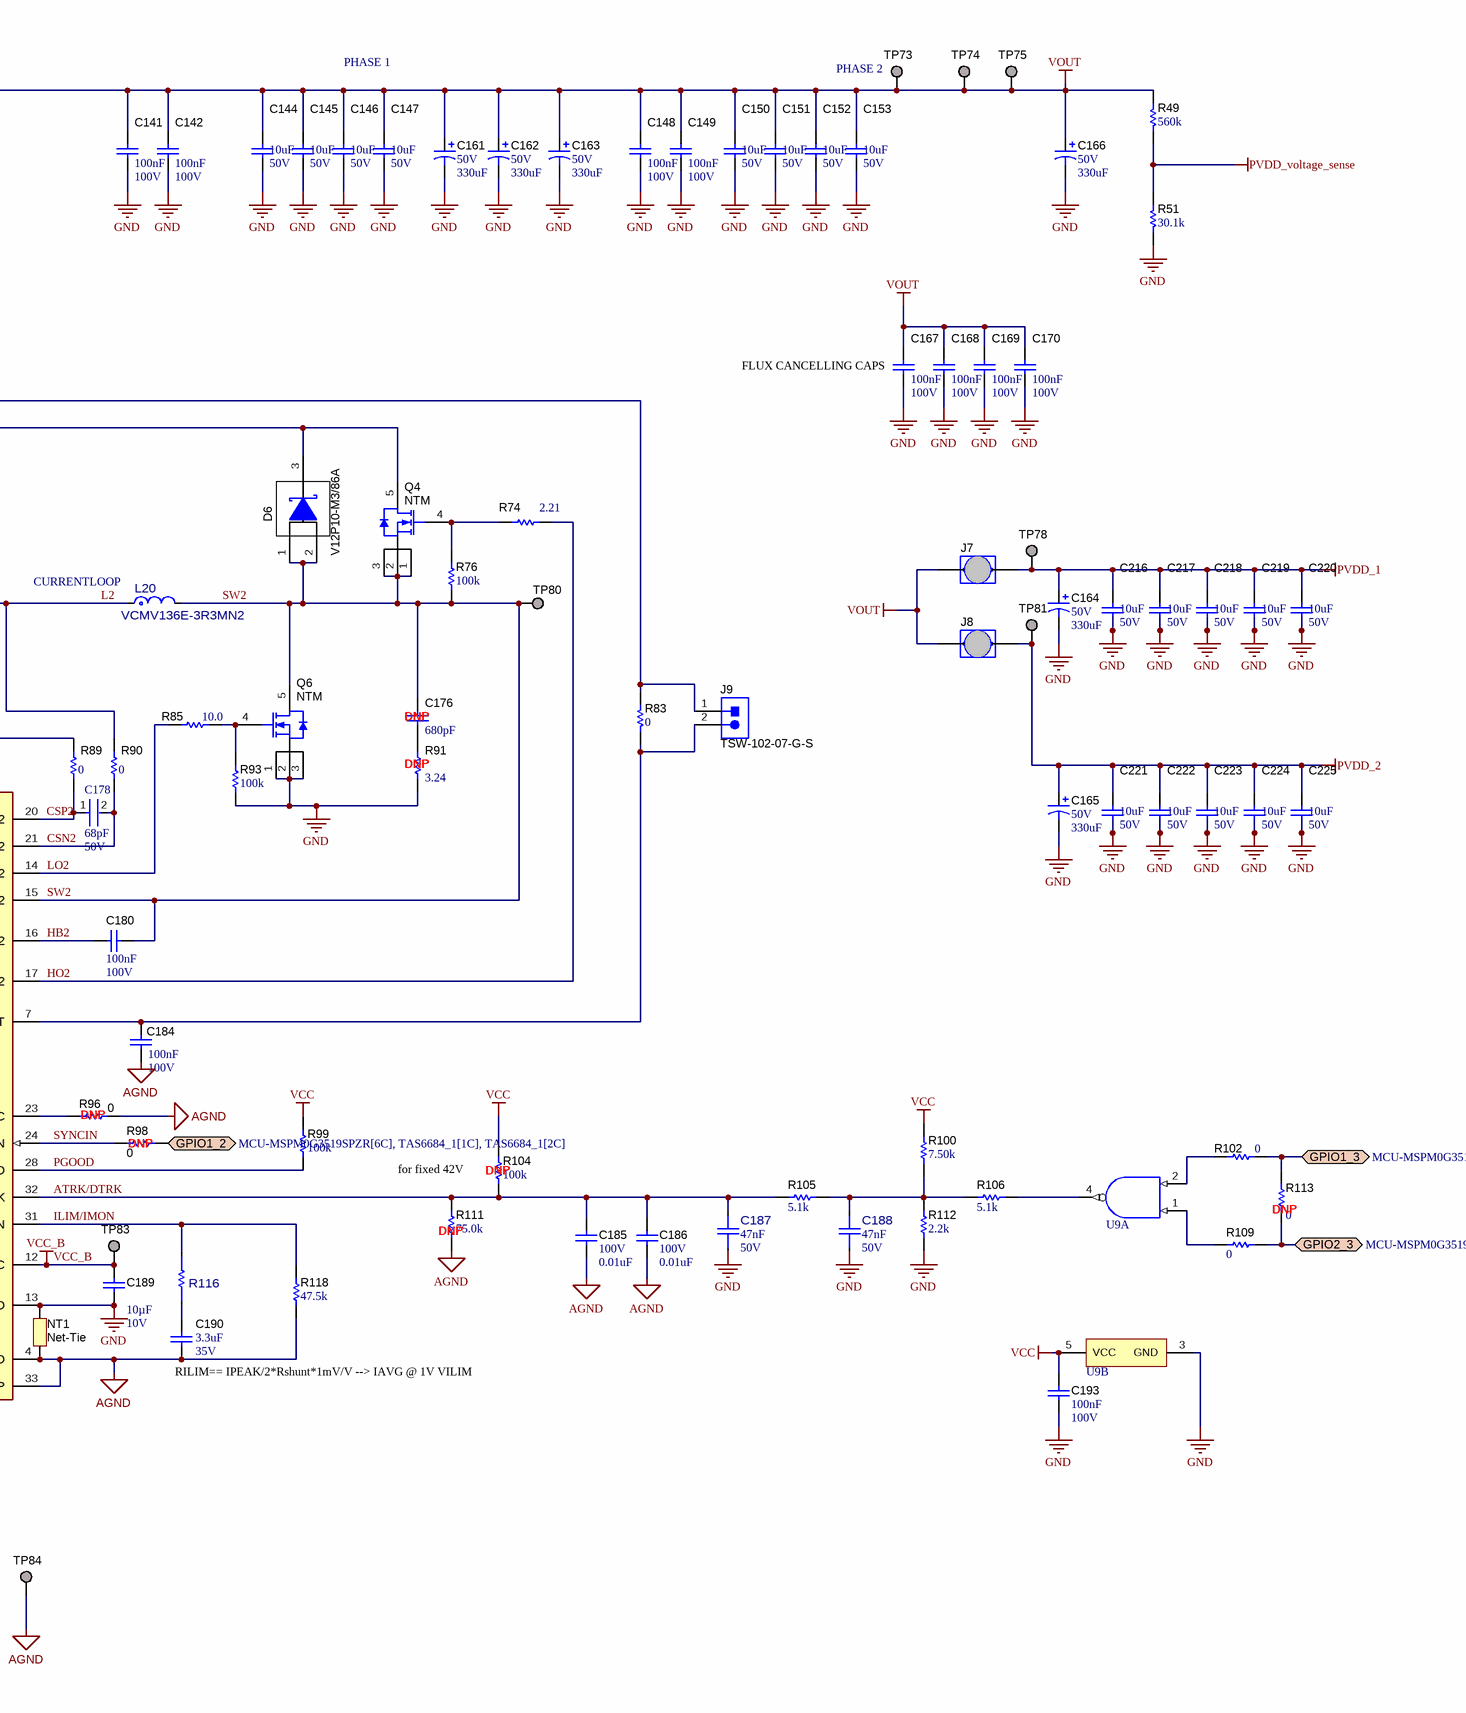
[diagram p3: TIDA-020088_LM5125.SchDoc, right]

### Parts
C141  Cap_F: 100nF  VDC_V: 100V  [0603]  (hidden comment: GCJ188R72A104KA01D)
C142  Cap_F: 100nF  VDC_V: 100V  [0603]  (hidden comment: GCJ188R72A104KA01D)
C144  ValueDisplayed: 10uF  VDC_V: 50V  [1210_280]  (hidden comment: UMK325AB7106KMHT)
C145  ValueDisplayed: 10uF  VDC_V: 50V  [1210_280]  (hidden comment: UMK325AB7106KMHT)
C146  ValueDisplayed: 10uF  VDC_V: 50V  [1210_280]  (hidden comment: UMK325AB7106KMHT)
C147  ValueDisplayed: 10uF  VDC_V: 50V  [1210_280]  (hidden comment: UMK325AB7106KMHT)
C148  Cap_F: 100nF  VDC_V: 100V  [0603]  (hidden comment: GCJ188R72A104KA01D)
C149  Cap_F: 100nF  VDC_V: 100V  [0603]  (hidden comment: GCJ188R72A104KA01D)
C150  ValueDisplayed: 10uF  VDC_V: 50V  [1210_280]  (hidden comment: UMK325AB7106KMHT)
C151  ValueDisplayed: 10uF  VDC_V: 50V  [1210_280]  (hidden comment: UMK325AB7106KMHT)
C152  ValueDisplayed: 10uF  VDC_V: 50V  [1210_280]  (hidden comment: UMK325AB7106KMHT)
C153  ValueDisplayed: 10uF  VDC_V: 50V  [1210_280]  (hidden comment: UMK325AB7106KMHT)
C155  ValueDisplayed: 10uF  VDC_V: 50V  [1210_280]  (hidden comment: UMK325AB7106KMHT)
C156  ValueDisplayed: 10uF  VDC_V: 50V  [1210_280]  (hidden comment: UMK325AB7106KMHT)
C157  ValueDisplayed: 10uF  VDC_V: 50V  [1210_280]  (hidden comment: UMK325AB7106KMHT)
C158  ValueDisplayed: 10uF  VDC_V: 50V  [1210_280]  (hidden comment: UMK325AB7106KMHT)
C159  ValueDisplayed: 330uF  VDC_V: 50V  [Nichicon_1000x1000]  (hidden comment: UCM1H331MNL1GS)
C160  ValueDisplayed: 330uF  VDC_V: 50V  [Nichicon_1000x1000]  (hidden comment: UCM1H331MNL1GS)
C161  VDC_V: 50V  ValueDisplayed: 330uF  [Nichicon_1000x1000]  (hidden comment: UCM1H331MNL1GS)
C162  VDC_V: 50V  ValueDisplayed: 330uF  [Nichicon_1000x1000]  (hidden comment: UCM1H331MNL1GS)
C163  VDC_V: 50V  ValueDisplayed: 330uF  [Nichicon_1000x1000]  (hidden comment: UCM1H331MNL1GS)
C164  VDC_V: 50V  ValueDisplayed: 330uF  [Nichicon_1000x1000]  (hidden comment: UCM1H331MNL1GS)
C165  VDC_V: 50V  ValueDisplayed: 330uF  [Nichicon_1000x1000]  (hidden comment: UCM1H331MNL1GS)
C166  VDC_V: 50V  ValueDisplayed: 330uF  [Nichicon_1000x1000]  (hidden comment: UCM1H331MNL1GS)
C167  Cap_F: 100nF  VDC_V: 100V  [0603]  (hidden comment: GCJ188R72A104KA01D)
C168  Cap_F: 100nF  VDC_V: 100V  [0603]  (hidden comment: GCJ188R72A104KA01D)
C169  Cap_F: 100nF  VDC_V: 100V  [0603]  (hidden comment: GCJ188R72A104KA01D)
C170  Cap_F: 100nF  VDC_V: 100V  [0603]  (hidden comment: GCJ188R72A104KA01D)
C175  DNP  value 680pF  [0603S]  (no BOM)
C176  DNP  value 680pF  [0603S]  (no BOM)
C177  Capacitance: 68pF  Voltage Rating: 50V  [FP-GCM155-0_05-IPC_B]  (hidden comment: GCM1555C1H680FA16D)
C178  Capacitance: 68pF  Voltage Rating: 50V  [FP-GCM155-0_05-IPC_B]  (hidden comment: GCM1555C1H680FA16D)
C179  Cap_F: 100nF  VDC_V: 100V  [0603]  (hidden comment: GCJ188R72A104KA01D)
C180  Cap_F: 100nF  VDC_V: 100V  [0603]  (hidden comment: GCJ188R72A104KA01D)
C181  Cap_F: 100nF  VDC_V: 100V  [0603]  (hidden comment: GCJ188R72A104KA01D)
C182  VDC_V: 100V  ValueDisplayed: 1µF  [1206]  (hidden comment: GCJ31CR72A105KA01K)
C183  Cap_F: 100nF  VDC_V: 100V  [0603]  (hidden comment: GCJ188R72A104KA01D)
C184  Cap_F: 100nF  VDC_V: 100V  [0603]  (hidden comment: GCJ188R72A104KA01D)
C185  VDC_V: 100V  ValueDisplayed: 0.01uF  [0603]  (hidden comment: CGA3E2X7R2A103K080AA)
C186  VDC_V: 100V  ValueDisplayed: 0.01uF  [0603]  (hidden comment: CGA3E2X7R2A103K080AA)
C187  Cap_F: 47nF  VDC_V: 50V  [FP-GCJ188R71H473KA12D_0603-MFG]  (hidden comment: GCJ188R71H473KA12D)
C188  Cap_F: 47nF  VDC_V: 50V  [FP-GCJ188R71H473KA12D_0603-MFG]  (hidden comment: GCJ188R71H473KA12D)
C189  Cap_F: 10µF  VDC_V: 10V  [0805_HV]  (hidden comment: C0805C106J8RACAUTO)
C190  VDC_V: 35V  ValueDisplayed: 3.3uF  [0805_HV]  (hidden comment: CGA4J1X7R1V335K125AC)
C191  VDC_V: 16V  ValueDisplayed: 0.015µF  [0603]  (hidden comment: C0603C153G4GAC7867)
C192  VDC_V: 50V  ValueDisplayed: 470pF  [0603]  (hidden comment: GCM1885C1H471JA16D)
C193  Cap_F: 100nF  VDC_V: 100V  [0603]  (hidden comment: GCJ188R72A104KA01D)
C194  VDC_V: 100V  ValueDisplayed: 10pF  [0603]  (hidden comment: GCM1885C2A100JA16D)
C195  ValueDisplayed: 0.33uF  [0603]  (hidden comment: CGA3E3X7R1H334K080AB)
C216  ValueDisplayed: 10uF  VDC_V: 50V  [1210_280]  (hidden comment: UMK325AB7106KMHT)
C217  ValueDisplayed: 10uF  VDC_V: 50V  [1210_280]  (hidden comment: UMK325AB7106KMHT)
C218  ValueDisplayed: 10uF  VDC_V: 50V  [1210_280]  (hidden comment: UMK325AB7106KMHT)
C219  ValueDisplayed: 10uF  VDC_V: 50V  [1210_280]  (hidden comment: UMK325AB7106KMHT)
C220  ValueDisplayed: 10uF  VDC_V: 50V  [1210_280]  (hidden comment: UMK325AB7106KMHT)
C221  ValueDisplayed: 10uF  VDC_V: 50V  [1210_280]  (hidden comment: UMK325AB7106KMHT)
C222  ValueDisplayed: 10uF  VDC_V: 50V  [1210_280]  (hidden comment: UMK325AB7106KMHT)
C223  ValueDisplayed: 10uF  VDC_V: 50V  [1210_280]  (hidden comment: UMK325AB7106KMHT)
C224  ValueDisplayed: 10uF  VDC_V: 50V  [1210_280]  (hidden comment: UMK325AB7106KMHT)
C225  ValueDisplayed: 10uF  VDC_V: 50V  [1210_280]  (hidden comment: UMK325AB7106KMHT)
D5  V12P10-M3/86A  [TO-277A]
D6  V12P10-M3/86A  [TO-277A]
J7  (no value)  [HARWIN_S1911-46R]
J8  (no value)  [HARWIN_S1911-46R]
J9  TSW-102-07-G-S  [TSW-102-07-G-S]
L19  VCMV136E-3R3MN2  [FP-VCMV136E-3R3MN2_SMT_IND_13MM45_12MM6-MFG]
L20  VCMV136E-3R3MN2  [FP-VCMV136E-3R3MN2_SMT_IND_13MM45_12MM6-MFG]
NT1  Net-Tie  [Net-Tie_10milWide_30milLong]  (net tie, no BOM)
Q3  NTM  [SO-8FL]
Q4  NTM  [SO-8FL]
Q5  NTM  [SO-8FL]
Q6  NTM  [SO-8FL]
R49  ValueDisplayed: 560k  [0603]  (hidden comment: CRCW0603560KFKEA)
R51  ValueDisplayed: 30.1k  [0603]  (hidden comment: CRCW060330K1FKEA)
R62  ValueDisplayed: 180k  [0603]  (hidden comment: CRCW0603180KJNEA)
R63  ValueDisplayed: 30.1k  [0603]  (hidden comment: CRCW060330K1FKEA)
R64  ValueDisplayed: 30.1k  [0603]  (hidden comment: CRCW060330K1FKEA)
R73  ValueDisplayed: 2.21  [0603]  (hidden comment: CRCW06032R21FKEA)
R74  ValueDisplayed: 2.21  [0603]  (hidden comment: CRCW06032R21FKEA)
R75  ValueDisplayed: 100k  [0402S]  (hidden comment: CRCW0402100KFKED)
R76  ValueDisplayed: 100k  [0402S]  (hidden comment: CRCW0402100KFKED)
R77  ValueDisplayed: 0.0015  [ULRB22512_085]  (hidden comment: ULRB22512R0015FLFSLT)
R78  ValueDisplayed: 0.0015  [ULRB22512_085]  (hidden comment: ULRB22512R0015FLFSLT)
R83  ValueDisplayed: 0  [0603]  (hidden comment: CRCW06030000Z0EA)
R84  ValueDisplayed: 10.0  [0603S]  (hidden comment: CRCW060310R0FKEA)
R85  ValueDisplayed: 10.0  [0603S]  (hidden comment: CRCW060310R0FKEA)
R86  DNP  ValueDisplayed: 3.24  [1206L]  (no BOM)
R87  ValueDisplayed: 0  [0603]  (hidden comment: CRCW06030000Z0EA)
R88  ValueDisplayed: 0  [0603]  (hidden comment: CRCW06030000Z0EA)
R89  ValueDisplayed: 0  [0603]  (hidden comment: CRCW06030000Z0EA)
R90  ValueDisplayed: 0  [0603]  (hidden comment: CRCW06030000Z0EA)
R91  DNP  ValueDisplayed: 3.24  [1206L]  (no BOM)
R92  ValueDisplayed: 100k  [0402S]  (hidden comment: CRCW0402100KFKED)
R93  ValueDisplayed: 100k  [0402S]  (hidden comment: CRCW0402100KFKED)
R94  ValueDisplayed: 180k  [0603]  (hidden comment: CRCW0603180KJNEA)
R96  DNP  ValueDisplayed: 0  [0603S]
R97  ValueDisplayed: 0  [0603]  (hidden comment: CRCW06030000Z0EA)
R98  DNP  ValueDisplayed: 0  [0603S]  (no BOM)
R99  ValueDisplayed: 100k  [0402S]  (hidden comment: CRCW0402100KFKED)
R100  ValueDisplayed: 7.50k  [0603]  (hidden comment: CRCW06037K50FKEA)
R101  DNP  ValueDisplayed: 0  [0603]  (no BOM)
R102  ValueDisplayed: 0  [0603]  (hidden comment: CRCW06030000Z0EA)
R103  ValueDisplayed: 0  [0603]  (hidden comment: CRCW06030000Z0EA)
R104  DNP  ValueDisplayed: 100k  [0402S]  (no BOM)
R105  ValueDisplayed: 5.1k  [0603]  (hidden comment: CRCW06035K10JNEA)
R106  ValueDisplayed: 5.1k  [0603]  (hidden comment: CRCW06035K10JNEA)
R107  ValueDisplayed: 10.0k  [0603]  (hidden comment: CRCW060310K0FKEA)
R109  ValueDisplayed: 0  [0603]  (hidden comment: CRCW06030000Z0EA)
R110  ValueDisplayed: 13.0k  [0603]  (hidden comment: CRCW060313K0FKEA)
R111  DNP  ValueDisplayed: 75.0k  [0603S]  (no BOM)
R112  ValueDisplayed: 2.2k  [0603]  (hidden comment: CRCW06032K20JNEA)
R113  DNP  ValueDisplayed: 0  [0603]  (no BOM)
R114  ValueDisplayed: 0  [0603]  (hidden comment: CRCW06030000Z0EA)
R115  DNP  ValueDisplayed: 0  [0603]
R116  ERA-3AEB622V  [FP-ERA-3AEB622V_0603-MFG]  (value not drawn)
R118  ValueDisplayed: 47.5k  [0603]  (hidden comment: CRCW060347K5FKEA)
R119  ValueDisplayed: 20.0k  [0603S]  (hidden comment: CRCW060320K0FKEA)
R120  ValueDisplayed: 78.7k  [0603]  (hidden comment: CRCW060378K7FKEA)
TP73  TP_SM_1MM  [TP_SM_1MM]  (value not drawn)  (no BOM)
TP74  TP_SM_1MM  [TP_SM_1MM]  (value not drawn)  (no BOM)
TP75  TP_SM_1MM  [TP_SM_1MM]  (value not drawn)  (no BOM)
TP76  TP_SM_1MM  [TP_SM_1MM]  (value not drawn)  (no BOM)
TP77  TP_SM_1MM  [TP_SM_1MM]  (value not drawn)  (no BOM)
TP78  TP_SM_1MM  [TP_SM_1MM]  (value not drawn)  (no BOM)
TP79  TP_SM_1MM  [TP_SM_1MM]  (value not drawn)  (no BOM)
TP80  TP_SM_1MM  [TP_SM_1MM]  (value not drawn)  (no BOM)
TP81  TP_SM_1MM  [TP_SM_1MM]  (value not drawn)  (no BOM)
TP83  TP_SM_1MM  [TP_SM_1MM]  (value not drawn)  (no BOM)
TP84  TP_SM_1MM  [TP_SM_1MM]  (value not drawn)  (no BOM)
U8  LM5125QRHBRQ1  [RHB0032U-MFG]
U9  SN74AHC1G00QDCKRQ1  [DCK0005A_N]  (value not drawn)  (parts A,B of 2)

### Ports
GPIO1_2 (bidir, see MCU-MSPM0G3519SPZR[6C], TAS6684_1[1C], TAS6684_1[2C]), GPIO1_3 (bidir, see MCU-MSPM0G3519SPZR[6C], TAS6684_1[2C]), GPIO2_3 (bidir, see MCU-MSPM0G3519SPZR[6C], TAS6684_2[2C])

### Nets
AGND: C181.2 C182.1 C183.2 C184.2 C185.2 C186.2 C190.2 C192.2 C194.2 C195.2 NT1.1 R64.2 R96.2 R101.2 R103.2 R107.1 R110.2 R111.1 R114.1 R118.1 R119.1 R120.1 TP84.1 U8.4(AGND) U8.33(EP)
BIAS: C155.1 C156.1 C157.1 C158.1 C159.1(+) C160.1(+) C182.2 C183.1 R62.1 R77.2 R78.1 R88.2 R89.2 R94.1 U8.18(BIAS)  [also labelled 14_4V]
EN2: R97.2 R101.1 U8.30(EN2)
GND: C141.2 C142.2 C144.2 C145.2 C146.2 C147.2 C148.2 C149.2 C150.2 C151.2 C152.2 C153.2 C155.2 C156.2 C157.2 C158.2 C159.2(-) C160.2(-) C161.2(-) C162.2(-) C163.2(-) C164.2(-) C165.2(-) C166.2(-) C167.2 C168.2 C169.2 C170.2 C187.1 C188.1 C189.2 C193.2 C216.2 C217.2 C218.2 C219.2 C220.2 C221.2 C222.2 C223.2 C224.2 C225.2 NT1.2 Q5.1(S) Q5.2(S) Q5.3(S) Q6.1(S) Q6.2(S) Q6.3(S) R51.2 R63.2 R86.1 R91.1 R92.1 R93.1 R112.1 TP76.1 TP77.1 U8.13(PGND) U9.3(GND)
Input_voltage_sense: R62.2 R63.1
MODE: R114.2 R115.1 U8.29(MODE)
PVDD_1: C164.1(+) C216.1 C217.1 C218.1 C219.1 C220.1 J7.2 TP78.1
PVDD_2: C165.1(+) C221.1 C222.1 C223.1 C224.1 C225.1 J8.2 TP81.1
PVDD_voltage_sense: R49.2 R51.1
UVLO/EN: C181.1 R64.1 R94.2 U8.19(UVLO/EN)
VCC: C193.1 R99.2 R100.2 R104.2 U9.5(VCC)
VCC_B: C189.1 R97.1 R115.2 TP83.1 U8.12(VCC)
VOUT: C141.1 C142.1 C144.1 C145.1 C146.1 C147.1 C148.1 C149.1 C150.1 C151.1 C152.1 C153.1 C161.1(+) C162.1(+) C163.1(+) C166.1(+) C167.1 C168.1 C169.1 C170.1 D5.3(K) D6.3(K) J7.1 J8.1 J9.1 Q3.5(D) Q4.5(D) R49.1 R83.1 TP73.1 TP74.1 TP75.1
ATRK/DTRK: C185.1 C186.1 C187.2 R104.1 R105.1 R111.2 U8.32(ATRK/DTRK)
CFG0: R110.1 U8.27(CFG0)
CFG1: R107.2 U8.26(CFG1)
CFG2: R103.1 U8.25(CFG2)
COMP: C191.1 C192.1 U8.3(COMP)
CSN1: C177.2 R87.1 U8.5(CSN1)
CSN2: C178.2 R90.1 U8.21(CSN2)
CSP1: C177.1 R88.1 U8.6(CSP1)
CSP2: C178.1 R89.1 U8.20(CSP2)
DLY: C194.1 U8.1(DLY)
HB1: C179.2 U8.9(HB1)
HB2: C180.1 U8.16(HB2)
HO1: R73.2 U8.8(HO1)
HO2: R74.1 U8.17(HO2)
ILIM/IMON: R116.2 R118.2 U8.31(ILIM/IMON)
L1: L19.2 R77.1 R87.2
L2: L20.1 R78.2 R90.2
LO1: R84.1 U8.11(LO1)
LO2: R85.2 U8.14(LO2)
PGOOD: R99.1 U8.28(PGOOD)
RT: R120.2 U8.22(RT)
SS: C195.1 U8.2(SS)
SW1: C175.1 C179.1 D5.1(A) D5.2(A) L19.1 Q3.1(S) Q3.2(S) Q3.3(S) Q5.5(D) R75.1 TP79.1 U8.10(SW1)
SW2: C176.1 C180.2 D6.1(A) D6.2(A) L20.2 Q4.1(S) Q4.2(S) Q4.3(S) Q6.5(D) R76.1 TP80.1 U8.15(SW2)
SYNCIN: R98.2 U8.24(SYNCIN)
NetC175_2: C175.2 R86.2
NetC176_2: C176.2 R91.2
NetC184_1: C184.1 J9.2 R83.2 U8.7(VOUT)
NetC188_2: C188.2 R100.1 R105.2 R106.1 R112.2
NetC190_1: C190.1 R116.1
NetC191_2: C191.2 R119.2
NetQ3_4: Q3.4(G) R73.1 R75.2
NetQ4_4: Q4.4(G) R74.2 R76.2
NetQ5_4: Q5.4(G) R84.2 R92.2
NetQ6_4: Q6.4(G) R85.1 R93.2
NetR5_1: R102.1 R113.1 ; port GPIO1_3
NetR6_1: R98.1 ; port GPIO1_2
NetR24_1: R109.2 R113.2 ; port GPIO2_3
NetR96_1: R96.1 U8.23(NC)
NetR102_2: R102.2 U9.2(B)
NetR106_2: R106.2 U9.4(Y)
NetR109_1: R109.1 U9.1(A)

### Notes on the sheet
- PHASE 2
- PHASE 1
- (near TP73) PHASE 2
- (near C159) VIN = 9V - 16V
- (near C167) FLUX CANCELLING CAPS
- CURRENTLOOP
- Ilim 36...44A
- VIN x 0.143
- (near C181) UVLO_on: 7.7V
- (near C181) UVLO_off: 5.7V
- UVLO/EN
- CFG2 DEM 1/10 Dither EN Icl_latch disable PGOODovp disable
- CFG3 internal clock syncin off
- for fixed 42V
- CFG1 dead time=200ns ATRK 20uA OFF
- configure the OVP to be 50V
- DEM mode
- FPWM mode
- (near C190) RILIM== IPEAK/2*Rshunt*1mV/V --> IAVG @ 1V VILIM

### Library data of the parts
C141 C142 C148 C149 C167-C170 C179-C181 C183 C184 = CMP-0064935-4: CAP, CERM, 0.1 uF, 100 V,+/- 10%, X7R, AEC-Q200 Grade 1, 0603; Manufacturer: MuRata; TaMin_C: -55°C; Polarized: N; SizeAreaWB_mm2: 4.68; Value1: Unknown; U/M: EA; Value: 0.1uF; TaMax_C: 125°C; SizeZ_mm: 1; SizeX_mm: 1.6; SizeY_mm: 0.8; SizeArea_mm2: 1.28; AEC Qualified: Y; AEC Category: Q200
C144-C147 C150-C153 C155-C158 C216-C225 = CMP-0009258-2: CAP, CERM, 10 uF, 50 V, +/- 10%, X7R, AEC-Q200 Grade 1, 1210; Manufacturer: Taiyo Yuden; AEC Qualified: Y; SizeZ_mm: 2.8; Cap_F: 10µF; AEC Grade: 1; Value: 10uF; TaMin_C: -55°C; Polarized: N; SizeAreaWB_mm2: 14.7; Value1: Unknown; U/M: EA; TaMax_C: 125°C; SizeX_mm: 3.2; SizeY_mm: 2.5; Cap_Case: 1210; SizeArea_mm2: 8; AEC Category: Q200
C159 C160 = CMP-0064900-1: as C115 on sheet TIDA-020088_Vbat_Input
C161-C166 = CMP-0064900-1: CAP, AL, 330 uF, 50 V, +/- 20%, SMD; Manufacturer: Nichicon; TaMin_C: -55°C; Polarized: Y; SizeAreaWB_mm2: 151.29; Value1: Unknown; U/M: EA; Value: 330uF; TaMax_C: 105°C; SizeZ_mm: 10.8; SizeX_mm: 10.3; Cap_Case: 10x10mm; SizeArea_mm2: 106.09; CompType: Capacitor; AEC Qualified: N; Cap_F: 330µF; IRMS_A: 900mA; AEC Category: Q200
C175 C176 = CMP-0006960-4: CAP, CERM, 680 pF, 50 V, +/- 10%, X7R, 0603; Manufacturer: Kemet; PartNumber: C0603C681K5RACTU; TaMin_C: -55°C; Polarized: N; SizeAreaWB_mm2: 4.68; Value1: Unknown; U/M: EA; TaMax_C: 125°C; SizeZ_mm: 1; SizeX_mm: 1.6; SizeY_mm: 0.8; Cap_Case: 0603; Value2: 50V; SizeArea_mm2: 1.28; AEC Category: Q200
C177 C178 = CMP-06035-033140-1: Ceramic Capacitor for Automotive 68pF ±1% 50VDC C0G 0402 Paper T/R
C182 = CMP-0750040-1: CAP, CERM, 1 µF, 100 V,+/- 10%, X7R, AEC-Q200 Grade 1, 1206; Manufacturer: MuRata; TaMin_C: -55°C; Polarized: N; SizeAreaWB_mm2: 10.92; U/M: EA; Value: 1uF; TaMax_C: 125°C; SizeZ_mm: 1.35; SizeX_mm: 3.2; SizeY_mm: 1.6; SizeArea_mm2: 5.12; AEC Qualified: Y; AEC Grade: 1; AEC Category: Q200
C185 C186 = CMP-0007082-4: CAP, CERM, 0.01 uF, 100 V, +/- 10%, X7R, AEC-Q200 Grade 1, 0603; Manufacturer: TDK; TaMin_C: -55°C; Polarized: N; SizeAreaWB_mm2: 4.68; Value1: 0.235428 ohm; U/M: EA; Value: 0.01uF; TaMax_C: 125°C; SizeZ_mm: 1; SizeX_mm: 1.6; SizeY_mm: 0.8; SizeArea_mm2: 1.28; AEC Qualified: Y; Cap_F: 10nF; AEC Category: Q200; ESR_ohm: 0.2354; IRMS_A: 396.995mA
C187 C188 = CMP-0084117-1: 0.047µF ±10% 50V Ceramic Capacitor X7R 0603 (1608 Metric); Manufacturer: Murata Electronics North America; AEC Qualified: Yes; SizeZ_mm: 0.9mm; AEC Grade: Grade 1; TempCo: 15%; Symbol Name: SYM-GCJ188R71H473KA12D
C189 = CMP-0081061-1: CAP, CERM, 10 µF, 10 V,+/- 5%, X7R, AEC-Q200 Grade 1, 0805; Manufacturer: Kemet; TaMin_C: -55°C; Polarized: N; SizeAreaWB_mm2: 6.75; U/M: EA; Value: 10uF; TaMax_C: 125°C; SizeZ_mm: 1.45; SizeX_mm: 2; SizeY_mm: 1.25; Cap_Case: 0805; SizeArea_mm2: 2.5; AEC Qualified: Y; AEC Grade: 1; AEC Category: Q200
C190 = CMP-0007963-2: CAP, CERM, 3.3 uF, 35 V, +/- 10%, X7R, AEC-Q200 Grade 1, 0805; Manufacturer: TDK; TaMin_C: -55°C; Polarized: N; SizeAreaWB_mm2: 6.75; Value1: 0.002798 ohm; U/M: EA; Value: 3.3uF; TaMax_C: 125°C; SizeZ_mm: 1.45; SizeX_mm: 2; SizeY_mm: 1.25; Cap_Case: 0805; SizeArea_mm2: 2.5; AEC Qualified: Y; Cap_F: 3.3µF; AEC Grade: 1; AEC Category: Q200; ESR_ohm: 2.798m; IRMS_A: 3.9016A
C191 = CMP-0080737-1: CAP, CERM, 0.015 µF, 16 V,+/- 2%, C0G/NP0, AEC-Q200 Grade 1, 0603; Manufacturer: Kemet; Cap_F: 15nF; SizeAreaWB_mm2: 4.68; SizeArea_mm2: 1.28; AEC Qualified: Y; AEC Category: Q200; Value: 0.015uF; TaMax_C: 125°C; SizeZ_mm: 1; Green_REACh: Passed; Polarized: N; TaMin_C: -55°C; SizeY_mm: 0.8; Green_Lifecycle: Active; U/M: EA; SizeX_mm: 1.6
C192 = CMP-0007127-4: CAP, CERM, 470 pF, 50 V, +/- 5%, C0G/NP0, AEC-Q200 Grade 1, 0603; Manufacturer: MuRata; TaMin_C: -55°C; Polarized: N; SizeAreaWB_mm2: 4.68; Value1: Unknown; U/M: EA; Value: 470pF; TaMax_C: 125°C; SizeZ_mm: 1; SizeX_mm: 1.6; SizeY_mm: 0.8; SizeArea_mm2: 1.28; AEC Qualified: Y; AEC Category: Q200
C193 = CMP-0064935-2: CAP, CERM, 0.1 uF, 100 V,+/- 10%, X7R, AEC-Q200 Grade 1, 0603; Manufacturer: MuRata; TaMin_C: -55°C; Polarized: N; SizeAreaWB_mm2: 4.68; Value1: Unknown; U/M: EA; Value: 0.1uF; TaMax_C: 125°C; SizeZ_mm: 1; SizeX_mm: 1.6; SizeY_mm: 0.8; SizeArea_mm2: 1.28; AEC Qualified: Y; AEC Category: Q200
C194 = CMP-0084283-1: as C119 on sheet TIDA-020088_Vbat_Input
C195 = CMP-0007095-4: CAP, CERM, 0.33 uF, 50 V, +/- 10%, X7R, AEC-Q200 Grade 1, 0603; Manufacturer: TDK; TaMin_C: -55°C; Polarized: N; SizeAreaWB_mm2: 4.68; Value1: 0.01584 ohm; U/M: EA; Value: 0.33uF; TaMax_C: 125°C; SizeZ_mm: 1; SizeX_mm: 1.6; SizeY_mm: 0.8; Value2: 50V; SizeArea_mm2: 1.28; AEC Qualified: Y; Cap_F: 330nF; AEC Category: Q200; ESR_ohm: 15.84m; IRMS_A: 1.3135A
D5 D6 = CMP-0028832-2: Diode, Schottky, 100 V, 12 A, AEC-Q101, TO-277A; Manufacturer: Vishay-Semiconductor; SizeArea_mm2: 30.875; Value: 100V; Vf_V: 700mV; TJmax_C: 150°C; SizeZ_mm: 1.2; AEC Category: Q101; Value2: 0.7V; Green_Lifecycle: Not Set; SizeY_mm: 4.75; Green_REACh: Incomplete; Value1: 12A; SizeX_mm: 6.5; AEC Qualified: Y; SizeAreaWB_mm2: 57.375
J7 J8 = CMP-0075020-1: JUMPER TIN SMD; Manufacturer: Harwin; PartNumber: S1911-46R; CNHeader: False; Green_Lifecycle: Active; Green_REACh: Passed; CompType: Jumper SMT
J9 = CMP-0075405-3: Header, 100mil, 2x1, Gold, TH; Manufacturer: Samtec; Pitch_mm: 2.54; Gender: Male; Cert_CSA: Y; Row_Count: 1; Cert_CULUS: N; Current_A: 6.3A; Green_Lifecycle: Active; Green_REACh: Passed; Voltage_V: 550V
L19 L20 = CMP-0122777-1: Power Choke Coil 3.3uH 20% 100kHz 22.9A 6.6mOhm, 13.45x12.6x6.3mm SMT AECQ200; Manufacturer: Cyntec; AEC Grade: Grade 1; AEC Qualified: Yes; DCR_ohm: 6.6m; Ind_H: 3.3µH; Isat: 35A; Material: Metal Dust; SizeZ_mm: 6.5mm
NT1 = CMP-0078142-6: Single point connection between nets.
Q3-Q6 = CMP-0000853-1: MOSFET, N-CH, 60 V, 71 A, SO-8FL; PartNumber: NTMFS5C670NLT1G; Alternate Manufacturer: None; Manufacturer: ON Semiconductor; Value2: 20 nC; QgTyp_nC: 20; VdsMax_V: 60V; Value1: 0.008; Rdson45_ohm: 8.8m; SizeAreaWB_mm2: 58.2725; AEC Category: Q101; SizeX_mm: 6.15; Vgs_V: 20V; IdsMax_A: 71A; SizeZ_mm: 1.1; SizeY_mm: 5.15; AEC Qualified: N; Value: 60V; SizeArea_mm2: 31.6725; U/M: EA
R49 = CMP-0022496-4: RES, 560 k, 1%, 0.1 W, AEC-Q200 Grade 0, 0603; Manufacturer: Vishay-Dale; Power_W: 100mW; TempCo: 100 ppm/C; Value: 560k; SizeX_mm: 1.6; SizeY_mm: 0.8; SizeZ_mm: 1; Value2: 0.1W; SizeArea_mm2: 1.28; AEC Qualified: Y; VDC_V: 75V; AEC Category: Q200; AEC Grade: 0
R51 R63 R64 = CMP-0022324-4: RES, 30.1 k, 1%, 0.1 W, AEC-Q200 Grade 0, 0603; Manufacturer: Vishay-Dale; Power_W: 100mW; TempCo: 100 ppm/C; Value_Code: 30k1; Value: 30.1k; SizeX_mm: 1.6; SizeY_mm: 0.8; SizeZ_mm: 1; Value2: 0.1W; SizeArea_mm2: 1.28; AEC Qualified: Y; VDC_V: 75V; AEC Category: Q200; AEC Grade: 0; EIA_Code: E96
R62 R94 = CMP-0025725-4: RES, 180 k, 5%, 0.1 W, AEC-Q200 Grade 0, 0603; Manufacturer: Vishay-Dale; Power_W: 100mW; TempCo: 200 ppm/C; Value: 180k; EIA_Code: E24; SizeX_mm: 1.6; SizeY_mm: 0.8; SizeZ_mm: 1; Value2: 0.1W; SizeArea_mm2: 1.28; AEC Qualified: Y; VDC_V: 75V; AEC Category: Q200; AEC Grade: 0
R73 R74 = CMP-0022306-4: RES, 2.21, 1%, 0.1 W, AEC-Q200 Grade 0, 0603; Manufacturer: Vishay-Dale; Power_W: 100mW; TempCo: 100 ppm/C; Value_Code: 2R21; Value: 2.21; EIA_Code: E96; SizeX_mm: 1.6; SizeY_mm: 0.8; SizeZ_mm: 1; Value2: 0.1W; SizeArea_mm2: 1.28; AEC Qualified: Y; VDC_V: 75V; AEC Category: Q200; AEC Grade: 0
R75 R76 R92 R93 R99 = CMP-0025950-3: RES, 100 k, 1%, 0.063 W, AEC-Q200 Grade 0, 0402; Manufacturer: Vishay-Dale; Power_W: 63mW; TempCo: 100 ppm/C; Value: 100k; EIA_Code: E96; SizeX_mm: 1; SizeY_mm: 0.5; SizeZ_mm: 0.6; Value2: 0.063W; AEC Qualified: Y; VDC_V: 50V; AEC Category: Q200; AEC Grade: 0
R77 R78 = CMP-0015847-2: RES, 0.0015, 1%, 2 W, AEC-Q200 Grade 0, 2512; Manufacturer: TT Electronics/IRC; Power_W: 2W; TempCo: 50 ppm/C; Value_Code: 1L500; U/M: EA; Value: 0.0015; Res_ohm: 1.5m; AEC Qualified: Y; AEC Grade: 0; AEC Category: Q200
R83 = CMP-0025697-4: RES, 0, 5%, 0.1 W, AEC-Q200 Grade 0, 0603; Manufacturer: Vishay-Dale; Power_W: 100mW; TempCo: 200 ppm/C; Value_Code: 0000; Value: 0; EIA_Code: E24; SizeX_mm: 1.6; SizeY_mm: 0.8; SizeZ_mm: 1; Value2: 0.1W; SizeArea_mm2: 1.28; AEC Qualified: Y; VDC_V: 75V; AEC Category: Q200
R84 R85 = CMP-0022003-4: RES, 10.0, 1%, 0.1 W, AEC-Q200 Grade 0, 0603; Manufacturer: Vishay-Dale; Power_W: 100mW; TempCo: 100 ppm/C; Value_Code: 10R0; Value: 10.0; EIA_Code: E96; Res_ohm: 10; SizeX_mm: 1.6; SizeY_mm: 0.8; SizeZ_mm: 1; Value2: 0.1W; SizeArea_mm2: 1.28; AEC Qualified: Y; VDC_V: 75V; AEC Category: Q200; AEC Grade: 0
R86 R91 = CMP-0016971-3: RES, 3.24, 1%, 0.25 W, AEC-Q200 Grade 0, 1206; Manufacturer: Vishay-Dale; PartNumber: CRCW12063R24FKEA; Power_W: 250mW; TempCo: 100 ppm/C; Value_Code: 3R24; Value: 3.24; EIA_Code: E96; SizeX_mm: 3.2; SizeY_mm: 1.6; SizeZ_mm: 1.35; Value2: 0.25W; SizeArea_mm2: 5.12; AEC Qualified: Y; VDC_V: 200V; AEC Category: Q200; AEC Grade: 0
R87-R90 R97 R102 R103 R109 R114 = CMP-0025697-4: as R157 on sheet TIDA-020088_Interface
R96 R98 = CMP-0023343-3: RES, 0, 1%, 0.1 W, AEC-Q200 Grade 0, 0603; Manufacturer: Stackpole Electronics Inc; PartNumber: RMCF0603ZT0R00; Power_W: 100mW; TempCo: ppm/C; U/M: EA; Value: 0; SizeX_mm: 1.6; SizeY_mm: 0.8; SizeZ_mm: 1; Value2: 0.1W; SizeArea_mm2: 1.28; AEC Qualified: Y; AEC Category: Q200
R100 = CMP-0022601-4: RES, 7.50 k, 1%, 0.1 W, AEC-Q200 Grade 0, 0603; Manufacturer: Vishay-Dale; Power_W: 100mW; TempCo: 100 ppm/C; Value_Code: 7k50; Value: 7.50k; EIA_Code: E96; Res_ohm: 7.5k; SizeX_mm: 1.6; SizeY_mm: 0.8; SizeZ_mm: 1; Value2: 0.1W; SizeArea_mm2: 1.28; AEC Qualified: Y; VDC_V: 75V; AEC Category: Q200; AEC Grade: 0
R101 R113 R115 = CMP-0025697-4: RES, 0, 5%, 0.1 W, AEC-Q200 Grade 0, 0603; Manufacturer: Vishay-Dale; PartNumber: CRCW06030000Z0EA; Power_W: 100mW; TempCo: 200 ppm/C; Value_Code: 0000; Value: 0; SizeX_mm: 1.6; SizeY_mm: 0.8; SizeZ_mm: 1; Value2: 0.1W; SizeArea_mm2: 1.28; AEC Qualified: Y; AEC Category: Q200; EIA_Code: E24; VDC_V: 75V
R104 = CMP-0025950-3: RES, 100 k, 1%, 0.063 W, AEC-Q200 Grade 0, 0402; Manufacturer: Vishay-Dale; PartNumber: CRCW0402100KFKED; Power_W: 63mW; TempCo: 100 ppm/C; Value: 100k; EIA_Code: E96; SizeX_mm: 1; SizeY_mm: 0.5; SizeZ_mm: 0.6; Value2: 0.063W; AEC Qualified: Y; VDC_V: 50V; AEC Category: Q200; AEC Grade: 0
R105 R106 = CMP-0025830-4: RES, 5.1 k, 5%, 0.1 W, AEC-Q200 Grade 0, 0603; Manufacturer: Vishay-Dale; Power_W: 100mW; TempCo: 200 ppm/C; Value_Code: 5k10; Value: 5.1k; SizeX_mm: 1.6; SizeY_mm: 0.8; SizeZ_mm: 1; Value2: 0.1W; SizeArea_mm2: 1.28; AEC Qualified: Y; VDC_V: 75V; AEC Category: Q200; AEC Grade: 0; EIA_Code: E24
R107 = CMP-0021998-4: as R155 on sheet TIDA-020088_Interface
R110 = CMP-0022042-4: RES, 13.0 k, 1%, 0.1 W, AEC-Q200 Grade 0, 0603; Manufacturer: Vishay-Dale; Power_W: 100mW; TempCo: 100 ppm/C; Value_Code: 13k0; Value: 13.0k; EIA_Code: E96; Res_ohm: 13k; SizeX_mm: 1.6; SizeY_mm: 0.8; SizeZ_mm: 1; Value2: 0.1W; SizeArea_mm2: 1.28; AEC Qualified: Y; VDC_V: 75V; AEC Category: Q200; AEC Grade: 0
R111 = CMP-0022589-4: RES, 75.0 k, 1%, 0.1 W, AEC-Q200 Grade 0, 0603; Manufacturer: Vishay-Dale; PartNumber: CRCW060375K0FKEA; Power_W: 100mW; TempCo: 100 ppm/C; Value_Code: 75k0; Value: 75.0k; EIA_Code: E96; Res_ohm: 75k; SizeX_mm: 1.6; SizeY_mm: 0.8; SizeZ_mm: 1; Value2: 0.1W; SizeArea_mm2: 1.28; AEC Qualified: Y; VDC_V: 75V; AEC Category: Q200; AEC Grade: 0
R112 = CMP-0025769-4: RES, 2.2 k, 5%, 0.1 W, AEC-Q200 Grade 0, 0603; Manufacturer: Vishay-Dale; Power_W: 100mW; TempCo: 200 ppm/C; Value_Code: 2k20; Value: 2.2k; SizeX_mm: 1.6; SizeY_mm: 0.8; SizeZ_mm: 1; Value2: 0.1W; SizeArea_mm2: 1.28; AEC Qualified: Y; VDC_V: 75V; AEC Category: Q200; AEC Grade: 0; EIA_Code: E24
R116 = CMP-0093991-1: 6.2 kOhms ±0.1% 0.1W, 1/10W Chip Resistor 0603 (1608 Metric) Automotive AEC-Q200 Thin Film; Manufacturer: Panasonic; Power_W: 100mW; TempCo: 25ppm/°C; Value: 6.2k; SizeZ_mm: 0.55mm; AEC Qualified: Yes; AEC Grade: Grade 0; VDC_V: 75V
R118 = CMP-0022439-4: RES, 47.5 k, 1%, 0.1 W, AEC-Q200 Grade 0, 0603; Manufacturer: Vishay-Dale; Power_W: 100mW; TempCo: 100 ppm/C; Value_Code: 47k5; Value: 47.5k; EIA_Code: E96; SizeX_mm: 1.6; SizeY_mm: 0.8; SizeZ_mm: 1; Value2: 0.1W; SizeArea_mm2: 1.28; AEC Qualified: Y; VDC_V: 75V; AEC Category: Q200; AEC Grade: 0
R119 = CMP-0022204-4: RES, 20.0 k, 1%, 0.1 W, AEC-Q200 Grade 0, 0603; Manufacturer: Vishay-Dale; Power_W: 100mW; TempCo: 100 ppm/C; Value_Code: 20k0; Value: 20.0k; EIA_Code: E96; Res_ohm: 20k; SizeX_mm: 1.6; SizeY_mm: 0.8; SizeZ_mm: 1; Value2: 0.1W; SizeArea_mm2: 1.28; AEC Qualified: Y; VDC_V: 75V; AEC Category: Q200; AEC Grade: 0
R120 = CMP-0022597-4: RES, 78.7 k, 1%, 0.1 W, AEC-Q200 Grade 0, 0603; Manufacturer: Vishay-Dale; Power_W: 100mW; TempCo: 100 ppm/C; Value_Code: 78k7; Value: 78.7k; EIA_Code: E96; SizeX_mm: 1.6; SizeY_mm: 0.8; SizeZ_mm: 1; Value2: 0.1W; SizeArea_mm2: 1.28; AEC Qualified: Y; VDC_V: 75V; AEC Category: Q200; AEC Grade: 0
TP73-TP81 TP83 TP84 = CMP-0003825-1: 1mm Test Point, SMT; Manufacturer: Any
U8 = CMP-0120194-1: Wide-VIN, 2.2 MHz dual-phase boost controller with VOUT tracking; Manufacturer: Texas Instruments; SizeZ_mm: 1mm; AEC Qualified: Yes; AEC Grade: Grade 1; Max Supply Voltage: 42V; Min Supply Voltage: 2.5V; Nominal Supply Current: 1500uA; Number Of Outputs: 1; Output Type: AdjustableProgrammable; Output Voltage: 6-60V; Standoff Height: 0mm; Switching Frequency: 100-2200kHz; TaMax_C: +125°C; TaMin_C: -40°C
U9 = CMP-0051741-1: Automotive Catalog Single Two-Input Positive-NAND Gate, DCK0005A, LARGE T&R; Manufacturer: Texas Instruments; Generic Part Number: SN74AHC1G00-Q1; Voltage(Nom)(V): 3.3,5; Input Type: CMOS; 3-State Output: No; Output Drive (IOL/IOH)(Max)(mA): 50/-50; Logic: True; Technology Family: AHC; ICC @ Nom Voltage(Max)(mA): 0.01; Bits(#): 1; VCC(Max)(V): 5.5; Gate Type: NAND; tpd @ Nom Voltage(Max)(ns): 11.4,7.5; VCC(Min)(V): 2; F @ Nom Voltage(Max)(Mhz): 75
